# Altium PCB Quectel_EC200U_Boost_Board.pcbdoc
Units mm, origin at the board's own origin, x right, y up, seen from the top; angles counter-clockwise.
Board outline 72.8 x 63.88 mm, 4 copper layers (Top Layer, Inner1, Inner2, Bottom Layer); 116 components, 85 nets, 444 pads, 106 vias.
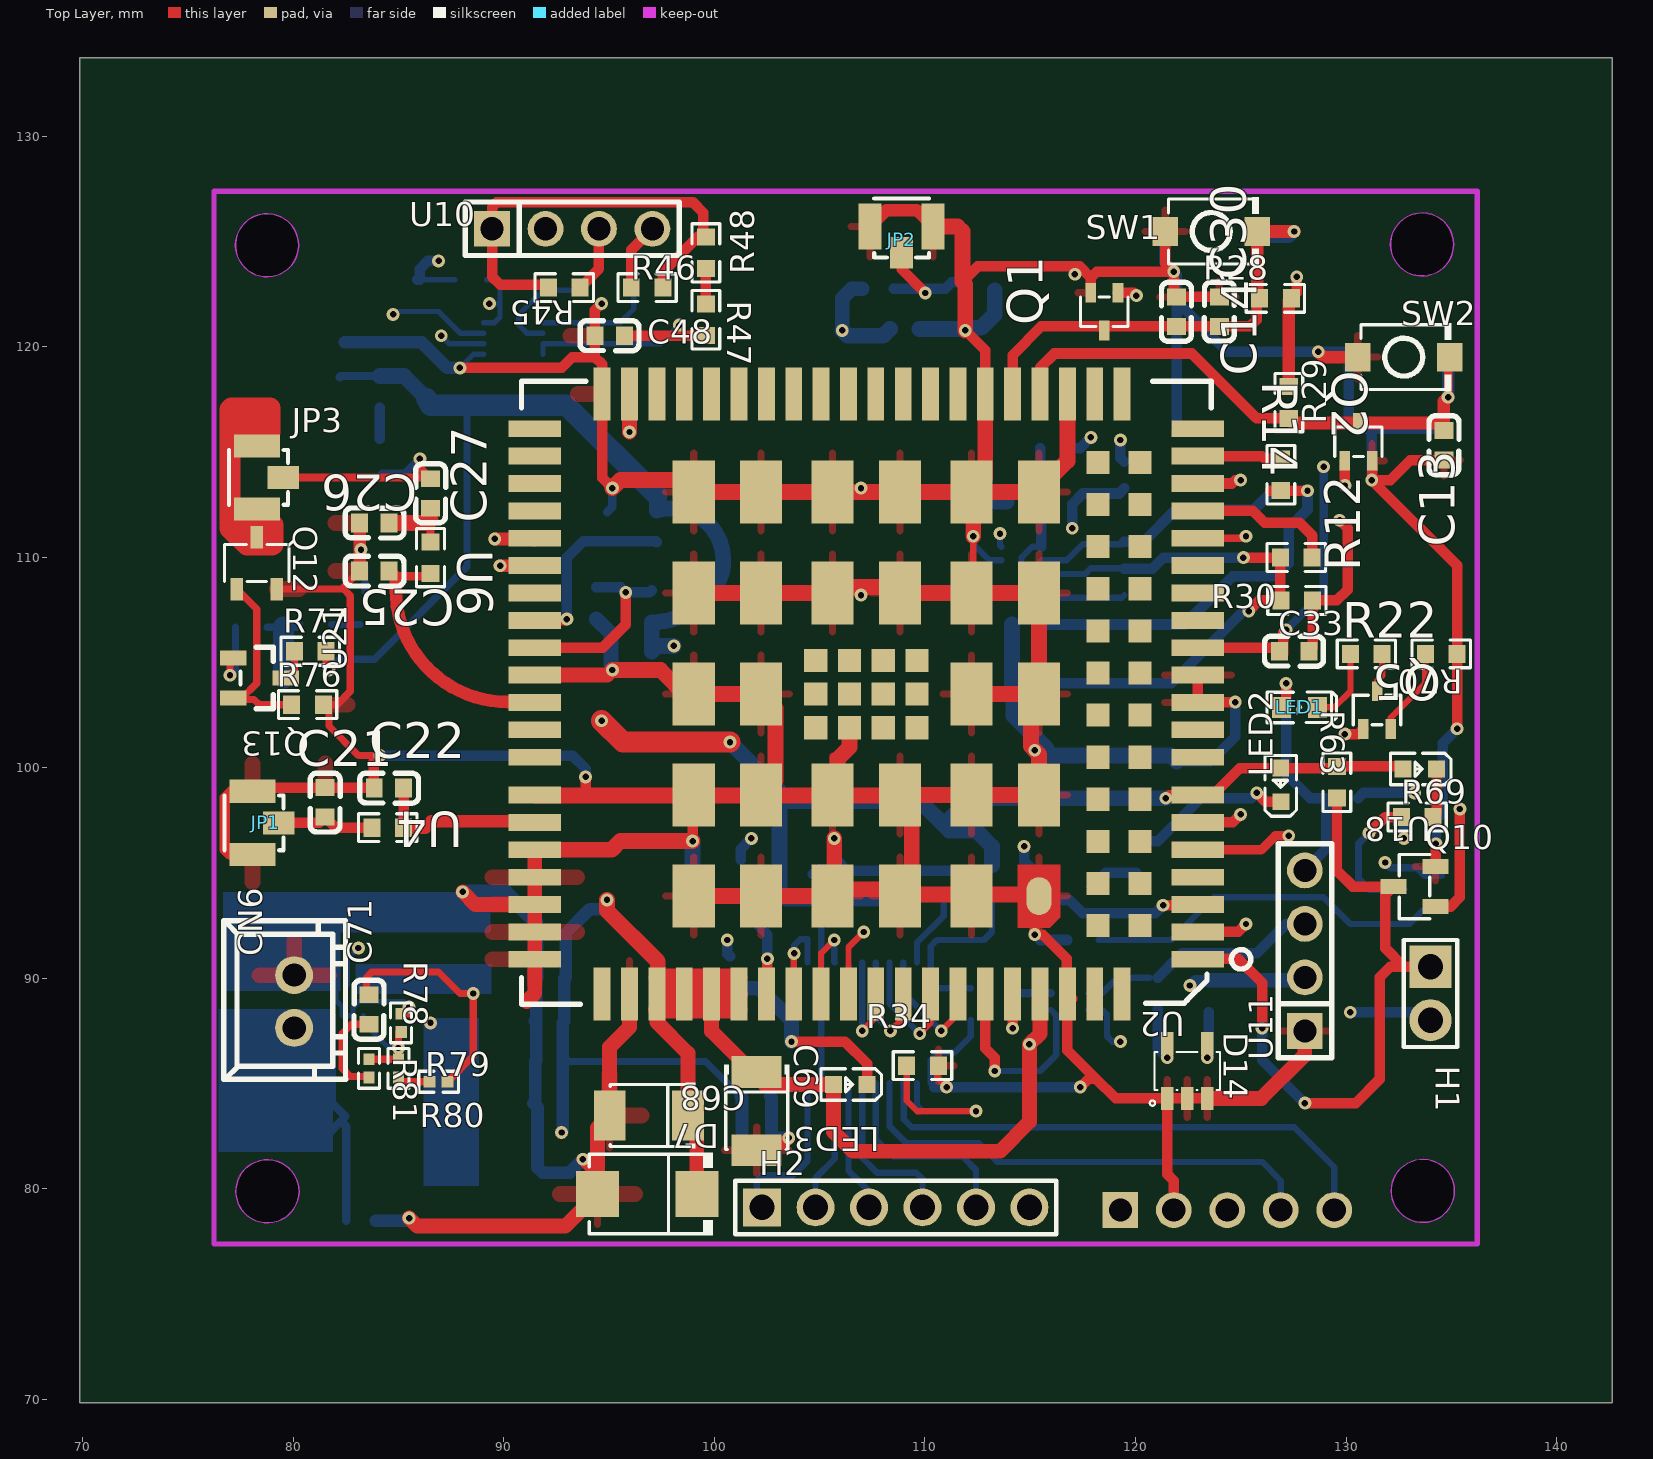
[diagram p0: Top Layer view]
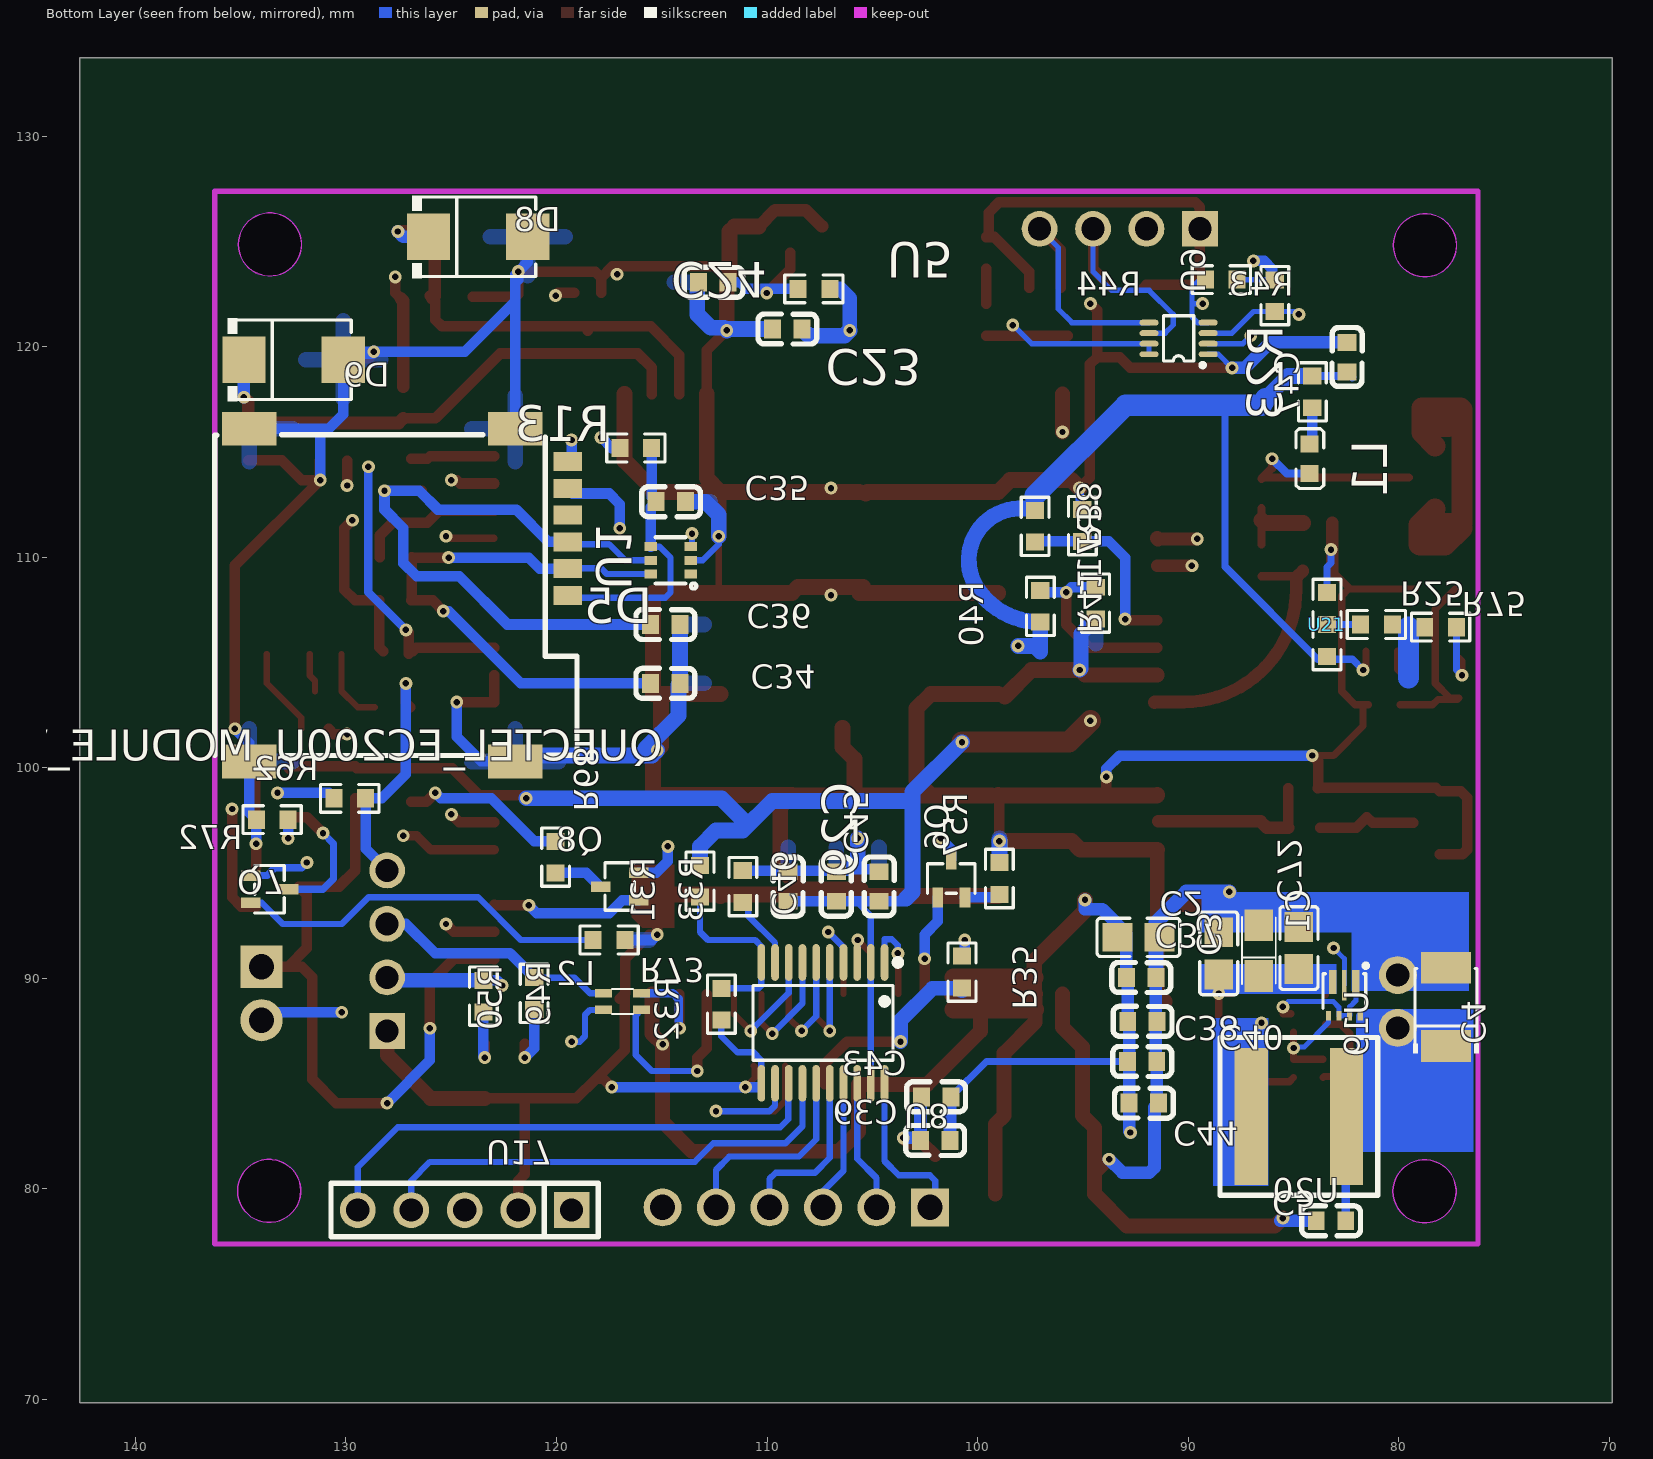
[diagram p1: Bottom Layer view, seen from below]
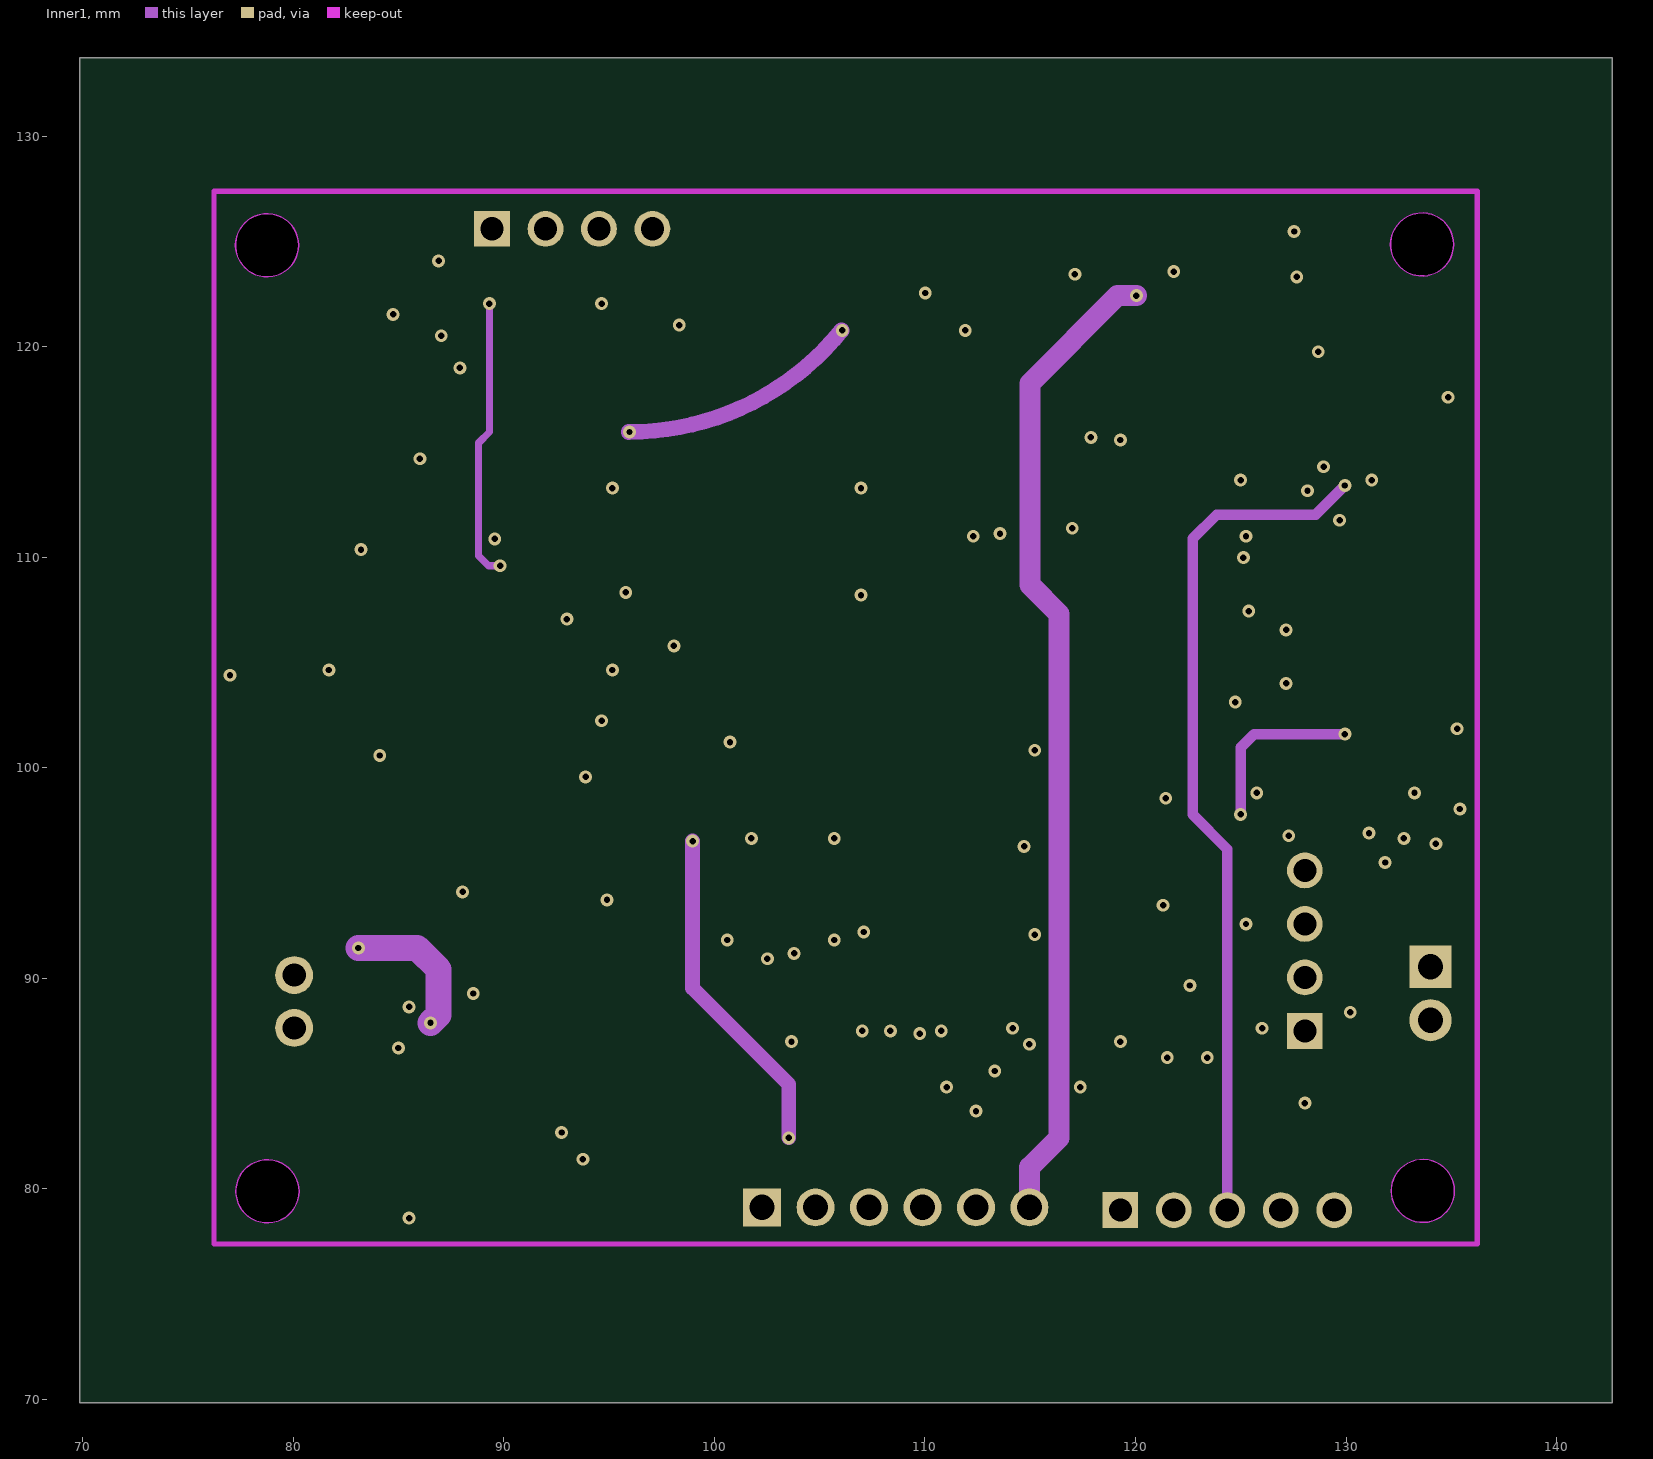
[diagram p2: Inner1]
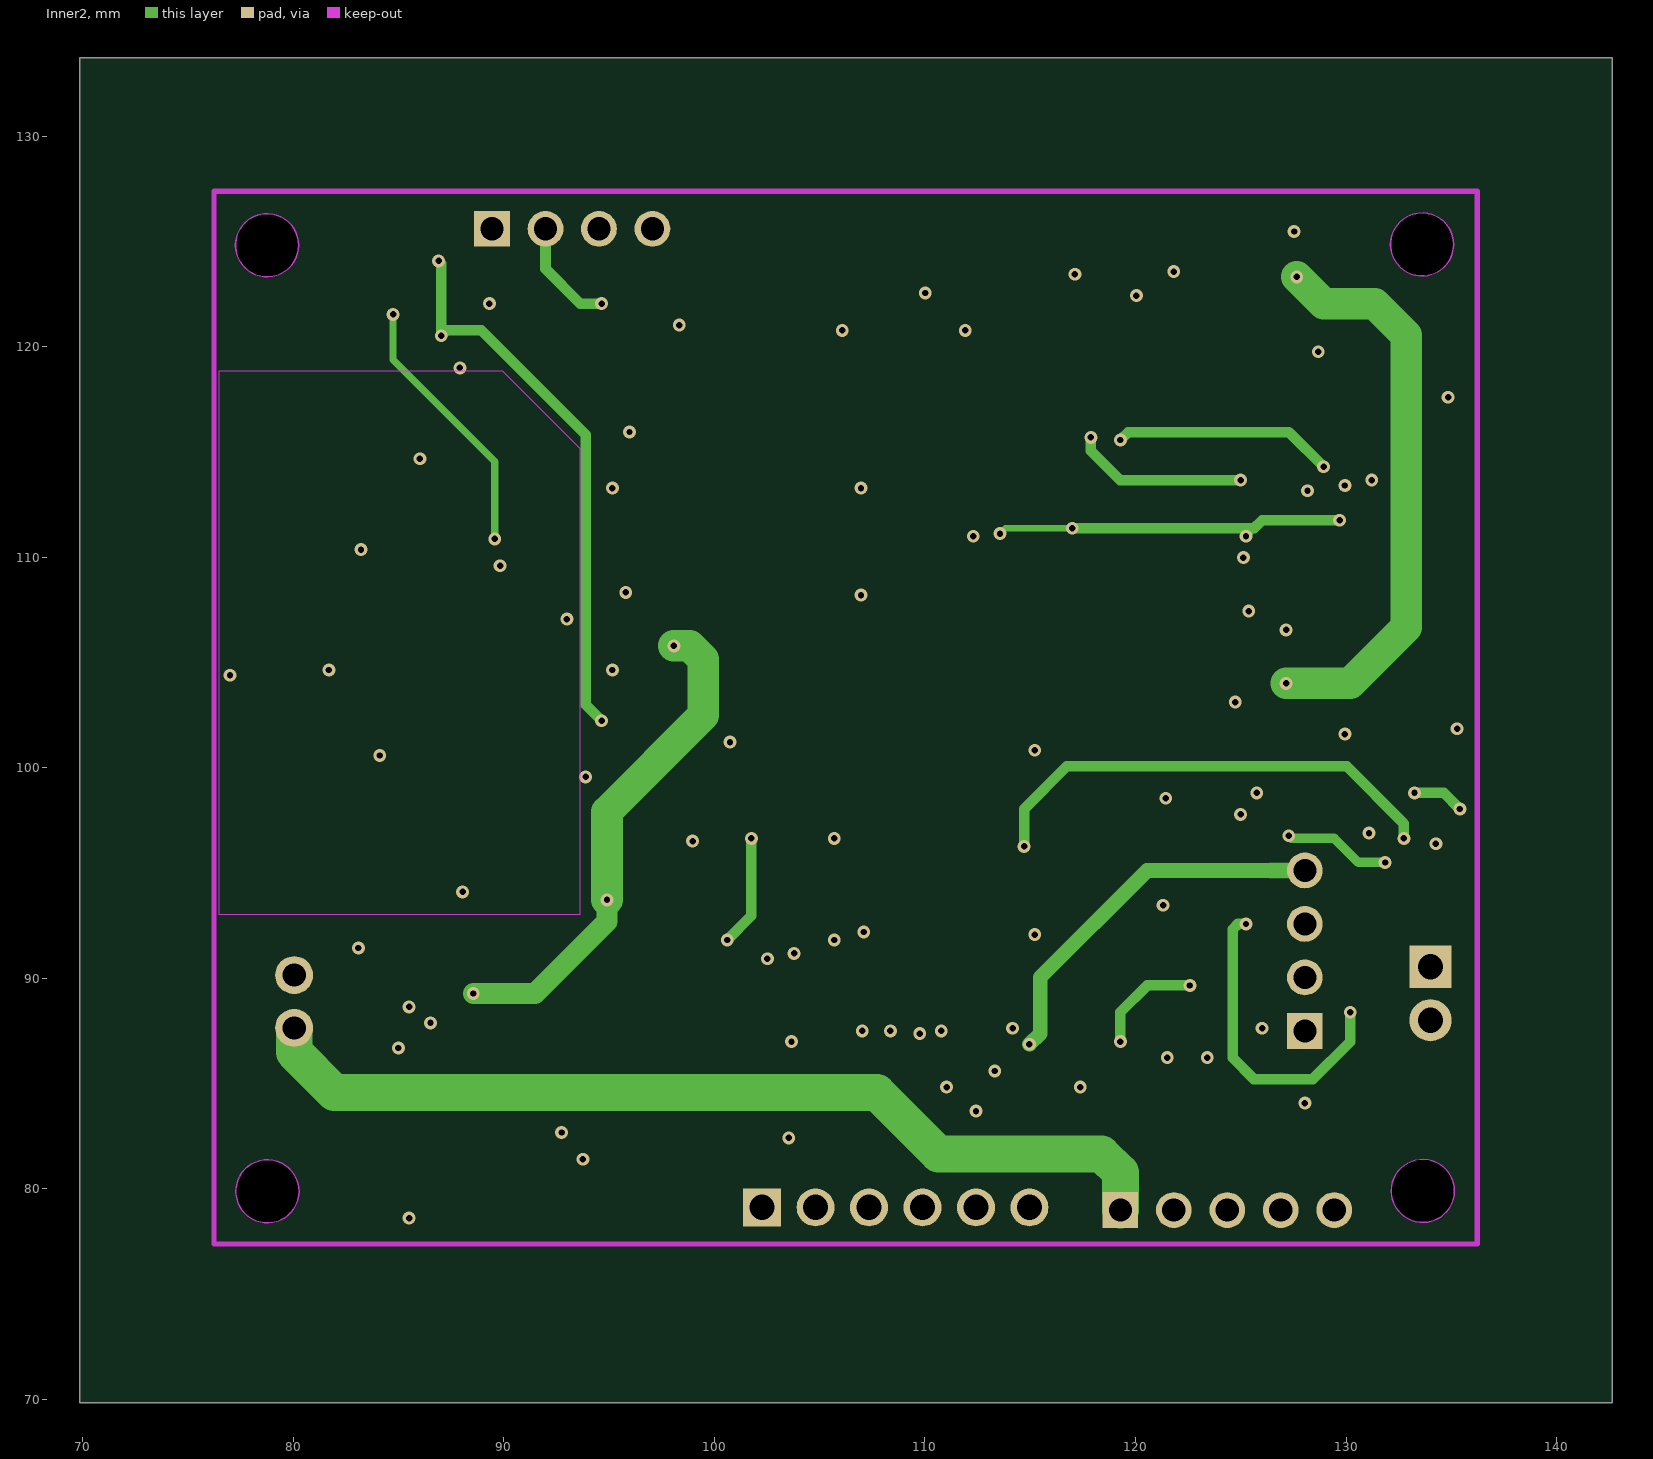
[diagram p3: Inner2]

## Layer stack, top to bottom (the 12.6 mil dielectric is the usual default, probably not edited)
Top Layer: signal copper (thickness not stored)
Dielectric: dielectric 0.32, FR-4, Dk 4.8
Inner1: signal copper (thickness not stored)
Dielectric: dielectric 0.32, FR-4, Dk 4.8
Inner2: signal copper (thickness not stored)
Dielectric: dielectric 0.32, FR-4, Dk 4.8
Bottom Layer: signal copper (thickness not stored)

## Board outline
142.649,69.85 69.85,69.85 69.85,133.731 142.649,133.731
cut-out: 80.268,79.883 cw(c78.768,79.883) 77.268,79.883 cw(c78.768,79.883)
cut-out: 135.15,79.903 cw(c133.65,79.903) 132.15,79.903 cw(c133.65,79.903)
cut-out: 135.112,124.859 cw(c133.612,124.859) 132.112,124.859 cw(c133.612,124.859)
cut-out: 80.25,124.821 cw(c78.75,124.821) 77.25,124.821 cw(c78.75,124.821)

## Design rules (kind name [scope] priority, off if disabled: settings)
BoardOutlineClearance Default [All] p0: genericclearance=0.254 ignorepadtopadclearanceinfootprint=FALSE except(0: Arc-SplitContinuation Track-SplitContinuation SMDPad-SplitContinuation THPad-SplitContinuation Via-SplitContinuation Fill-SplitContinuation Poly-SplitContinuation Region-SplitContinuation Text-SplitContinuation; 0.152: Track-OutlineEdge SMDPad-OutlineEdge THPad-OutlineEdge Via-OutlineEdge Fill-OutlineEdge Region-OutlineEdge Poly-OutlineEdge Text-OutlineEdge Track-CutoutEdge SMDPad-CutoutEdge THPad-CutoutEdge Via-CutoutEdge Fill-CutoutEdge Region-CutoutEdge)
Clearance Default [(InNet('I2C_SCL') OR InNet('VDD_EXT') OR InNet('PWRKEY') OR InNet('RSTKEY') OR InNet('SIM_GND') OR InNet('SIM_VDD') OR InNet('RF_ANT') OR InNet('WIFI/BT_ANT') OR InNet('GNSS_ANT') OR InNet('NW') OR InNet('MAIN_RXD') OR InNet('MAIN_TXD') OR InNet('SIM_CLK') OR InNet('ADC0') OR InNet('ADC1') OR InNet('SIM_DATA') OR InNet('SIM_RST') OR InNet('RKEY') OR InNet('I2C_SDA') OR InNet('PKEY') OR InNet('GND') OR InNet('$1N28') OR InNet('$1N29') OR InNet('$1N30') OR InNet('$1N1314') OR InNet('VBAT') OR InNet('$1N59') OR InNet('$1N67') OR InNet('MCU_TXD') OR InNet('MCU_RXD') OR InNet('MAIN_RI') OR InNet('MAIN_DCD') OR InNet('MAIN_CTS') OR InNet('MAIN_RTS') OR InNet('MAIN_DTR') OR InNet('MCU_RI') OR InNet('MCU_DCD') OR InNet('MCU_CTS') OR InNet('MCU_RTS') OR InNet('MCU_DTR') OR InNet('STATUS') OR InNet('$3N5800') OR InNet('$3N510') OR InNet('$3N512') OR InNet('I2C_SDA2') OR InNet('I2C_SCL2') OR InNet('$3N2253') OR InNet('VCC(3.3V)') OR InNet('$3N3340') OR InNet('$3N3620') OR InNet('$3N3623') OR InNet('USB_DP') OR InNet('USB_DM') OR InNet('$3N3933') OR InNet('$3N3934') OR InNet('NW_MODE') OR InNet('$3N5937') OR InNet('SLEEP_IND') OR InNet('$3N6076') OR InNet('WAKEUP_IN') OR InNet('$3N6217') OR InNet('AP_READY') OR InNet('$3N8732') OR InNet('$3N8771') OR InNet('$3N8850') OR InNet('$3N8845') OR InNet('$1N55959') OR InNet('VCC(2.5V-5V)') OR InNet('$1N55963') OR InNet('$1N55965') OR InNet('$1N55970') OR InNet('$1N42326') OR InNet('$1N42264') OR InNet('$1N42256') OR InNet('$1N42291') OR InNet('$1N42272') OR InNet('$1N42271') OR InNet('GNNS_SIN') OR InNet('GNSS_GND') OR InNet('$1N69113') OR InNet('GNSS_GND_TRG') OR InNet('$1N60604') OR InNet('$1N60546') OR InNet('$1N69275') OR InNet('$1N85973'))] p1: gap=0.178 ignorepadtopadclearanceinfootprint=FALSE except(0: Poly-Poly; 0.152: Track-Track Track-SMDPad SMDPad-SMDPad Track-THPad SMDPad-THPad THPad-THPad Track-Via SMDPad-Via THPad-Via Via-Via Track-Fill SMDPad-Fill THPad-Fill Via-Fill Fill-Fill Track-Region SMDPad-Region THPad-Region Via-Region Fill-Region Region-Region Track-Poly SMDPad-Poly THPad-Poly Via-Poly Fill-Poly Region-Poly Track-Text SMDPad-Text THPad-Text Via-Text Fill-Text Region-Text Poly-Text Text-Text Track-Sheet SMDPad-Sheet THPad-Sheet Via-Sheet Fill-Sheet Region-Sheet Poly-Sheet Text-Sheet Track-Hole SMDPad-Hole THPad-Hole Via-Hole Fill-Hole Region-Hole Poly-Hole Text-Hole Sheet-Hole)
DiffPairsRouting differentialPair [All] p1: maxuncoupledlength=10 minlimit=5.9843 maxlimit=5.9843 mostfreqgap=5.9843 toplayer_minwidth=5 toplayer_prefwidth=10 toplayer_maxwidth=100 bottomlayer_minwidth=5 bottomlayer_prefwidth=10 bottomlayer_maxwidth=100 midlayer1_minwidth=5 midlayer1_prefwidth=10 midlayer1_maxwidth=100 midlayer2_minwidth=5 midlayer2_prefwidth=10 midlayer2_maxwidth=100
PasteMaskExpansion Common [All] p1: expansion=0
PlaneConnect Default [All] p1: planeconnectstyle=Relief reliefexpansion=0.508 reliefentries=4 reliefconductorwidth=0 reliefairgap=0.254
PolygonConnect copperRegion [All] p1: connectstyle=Relief reliefentries=4 reliefconductorwidth=10 polygonreliefangle="90 Angle" airgapwidth=10
PolygonConnect TOP_poly [All] p1: connectstyle=Relief reliefentries=4 reliefconductorwidth=13.3858 polygonreliefangle="90 Angle" airgapwidth=13.3858
PolygonConnect RF_poly [All] p1: connectstyle=Relief reliefentries=4 reliefconductorwidth=29.5276 polygonreliefangle="90 Angle" airgapwidth=29.5276
RoutingVias Default [All] p1: viastyle="Through Hole" holewidth=12.0078 minholewidth=12.0078 maxholewidth=2362.0078 width=24.0158 minwidth=24.0158 maxwidth=3937.9922
SolderMaskExpansion Common [All] p1: useseparateexpansions=TRUE expansion=2.0079 expansionbottom=2.0079
Width Default [All] p1: maxlimit=236 minlimit=8 preferedwidth=10

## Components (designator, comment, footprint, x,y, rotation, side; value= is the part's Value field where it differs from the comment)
C1 "" C0805 84.737,91.44 r270 bottom
C2 "" C0805 92.357,91.948 r0 bottom
C3 "" C0805 88.547,91.186 r270 bottom
C4 "" CASE-B_3528 77.752,88.646 r90 bottom
C5 "" C0603 83.213,78.486 r0 bottom
C13 "10uF" C0603 134.648,115.316 r270 top
C14 "10uF" C0603 121.948,121.666 r90 top
C21 "NM" C0603 81.512,98.358 r90 top
C22 "NM" C0603 84.539,99.039 r180 top
C23 "NM" C0603 109.043,120.845 r0 bottom
C24 "NM" C0603 112.55,123.063 r0 bottom
C25 "NM" C0603 83.848,109.347 r180 top
C26 "NM" C0603 83.848,111.633 r180 top
C27 "100pF" C0603 86.515,113.03 r270 top
C29 "2.2uF" C0603 104.676,94.361 r270 bottom
C30 "10nF" C0603 123.98,121.666 r270 top
C33 "" C0603 127.536,105.537 r0 top
C34 "" C0603 114.836,104.013 r0 bottom
C35 "" C0603 114.567,112.64 r0 bottom
C36 "" C0603 114.836,106.807 r0 bottom
C37 "" C0603 92.23,90.043 r0 bottom
C38 "" C0603 92.186,86.055 r0 bottom
C39 "" C0603 102.009,82.296 r180 bottom
C40 "" C0603 92.17,87.96 r0 bottom
C43 "" C0603 101.962,84.374 r180 bottom
C44 "" C0603 92.103,84.074 r0 bottom
C45 "" C0603 106.708,94.361 r90 bottom
C46 "" C0603 108.994,94.361 r90 bottom
C47 "" C0603 82.451,119.507 r270 bottom
C48 "" C0603 95.024,120.523 r0 top
C68 "" CASE-B_3528 96.882,83.485 r180 top
C69 "" CASE-B_3528 102.009,83.693 r270 top
C71 "" C0603 83.594,88.519 r90 top
C72 "" CASE-A_3216 86.642,91.313 r90 bottom
CN6 "" CONN-TH_XH-2A 80.038,88.9 r90 top
D5 "SMF05C.TCT" SC-70-6_L2.2-W1.3-P0.65-LS2.1-BR 114.582,109.855 r180 bottom
D7 "" SMB_L4.6-W3.6-LS5.3-RD 96.802,79.756 r180 top
D8 "" SMB_L4.6-W3.6-LS5.3-RD 123.726,125.222 r180 bottom
D9 "" SMB_L4.6-W3.6-LS5.3-RD 132.489,119.38 r180 bottom
D14 "" SOT-23-5_L3.0-W1.7-P0.95-LS2.8-BR 122.456,85.598 r270 top
H1 "" HDR-TH_2P-P2.54-V-M 134.013,89.281 r270 top
H2 "" HDR-TH_6P-P2.54-V-M-1 108.613,79.121 r0 top
JP1 "" ANT-SMD_UFL-R-SMT-1-10 78.68,97.384 r180 top
JP2 "U.FL-R-SMT-1(10)" ANT-SMD_UFL-R-SMT-1-10 108.889,125.091 r90 top
JP3 "" ANT-SMD_UFL-R-SMT-1-10 78.895,113.792 r180 top
L1 "47nH" IND-SMD_L1.6-W0.8-1 84.229,114.681 r270 bottom
L2 "" IND-SMD_4P-L2.0-W1.2-TL 116.868,88.9 r180 bottom
LED1 "LED-0603_G" LED0603_GREEN 127.79,102.87 r0 top
LED2 "" LED0603-RD_BLUE 126.901,99.187 r90 top
LED3 "" LED0603-RD 106.454,84.963 r180 top
Q1 "DTC043EUBTL" SOT-323-3_L2.0-W1.3-P1.30-LS2.1-BR 118.519,121.666 r90 top
Q2 "DTC043EUBTL" SOT-323-3_L2.0-W1.3-P1.30-LS2.1-BR 130.588,115.483 r270 top
Q5 "DTC043EUBTL" SOT-323-3_L2.0-W1.3-P1.30-LS2.1-BR 131.473,102.743 r270 top
Q6 "" SOT-323-3_L2.0-W1.3-P1.30-LS2.1-BR 101.247,94.742 r270 bottom
Q7 "" SOT-323-3_L2.0-W1.3-P1.30-LS2.1-BR 133.632,94.234 r0 bottom
Q8 "" SOT-323-3_L2.0-W1.3-P1.30-LS2.1-BR 116.995,94.361 r180 bottom
Q10 "" SOT-23-3_L2.9-W1.3-P1.90-LS2.4-BR 133.251,94.361 r0 top
Q12 "" SOT-23-3_L2.9-W1.6-P1.90-LS2.8-BR 78.26,109.728 r270 top
Q13 "" SOT-23-3_L2.9-W1.3-P1.90-LS2.4-TR 78.387,104.267 r180 top
R12 "0Ω" R0603 127.635,109.991 r180 top
R13 "0Ω" R0603 116.233,115.189 r180 bottom
R14 "0Ω" R0603 126.901,113.919 r270 top
R22 "2.2kΩ" R0603 130.965,105.41 r0 top
R23 "10Ω" R0603 84.102,117.856 r270 bottom
R25 "" R0603 81.054,106.807 r0 bottom
R28 "" R0603 126.647,122.301 r0 top
R29 "" R0603 127.282,117.348 r90 top
R30 "" R0603 127.663,107.95 r0 top
R31 "" R0603 113.185,94.615 r270 bottom
R32 "" R0603 112.169,88.773 r270 bottom
R33 "" R0603 111.153,94.361 r270 bottom
R34 "" R0603 109.883,85.852 r0 top
R35 "2.2kΩ" R0603 100.739,90.297 r90 bottom
R38 "" R0603 97.269,111.469 r90 bottom
R40 "" R0603 97.02,107.669 r270 bottom
R41 "" R0603 94.389,107.823 r90 bottom
R43 "" R0603 85.88,122.428 r90 bottom
R44 "" R0603 88.42,123.19 r180 bottom
R45 "" R0603 92.865,122.809 r180 top
R46 "" R0603 96.802,122.809 r0 top
R47 "" R0603 99.596,121.285 r90 top
R48 "" R0603 99.596,124.46 r90 top
R49 "" R0603 121.059,89.281 r270 bottom
R50 "" R0603 123.472,89.154 r270 bottom
R57 "0Ω" R0603 98.961,94.742 r270 bottom
R62 "" R0603 129.822,98.552 r180 bottom
R63 "" R0603 129.568,99.314 r270 top
R68 "" R0603 120.043,95.758 r90 bottom
R69 "" R0603 133.378,97.663 r0 top
R70 "" R0603 134.521,105.41 r180 top
R71 "" R0603 95.024,111.506 r270 bottom
R72 "" R0603 133.505,97.536 r180 bottom
R73 "" R0603 117.503,91.821 r0 bottom
R75 "" R0603 78.006,106.68 r180 bottom
R76 "" R0603 80.673,102.997 r0 top
R77 "" R0603 80.8,105.537 r180 top
R78 "" R0402 85.118,87.884 r270 top
R79 "" R0402 84.991,85.725 r270 top
R80 "" R0402 86.896,85.09 r0 top
R81 "" R0402 83.594,85.725 r270 top
SW1 "" SW-SMD_L3.9-W3.0-P4.45 123.599,125.476 r0 top
SW2 "" SW-SMD_L3.9-W3.0-P4.45 132.743,119.507 r0 top
U1 "SIM-MICRO-6P" MICRO-SIM-SMD_KH-SIM1616-6PIN 127.028,108.204 r270 bottom
U2 "" LCC-LGA-144_L32.0-W29.0-CAT1-CUIOT-MZ-6 107.216,103.505 r180 top
U4 "CR0603-J/-000ELF" R0603 84.483,97.155 r180 top
U5 "CR0603-J/-000ELF" R0603 107.773,122.75 r0 bottom
U6 "CR0603-J/-000ELF" R0603 86.515,109.982 r90 top
U8 "" TSSOP-20_L6.5-W4.4-P0.65-LS6.4-BL 107.343,87.884 r0 bottom
U9 "" VSSOP-8_L2.3-W2.0-P0.50-LS3.1-BL 90.452,120.396 r90 bottom
U10 "" HDR-TH_4P-P2.54-V-M 93.246,125.603 r0 top
U11 "" HDR-TH_4P-P2.54-V-M 128.044,91.313 r90 top
U17 "" HDR-TH_5P-P2.54-V-M 124.361,78.994 r0 bottom
U18 "" LED0603-RD 133.505,99.949 r180 top
U19 "" VQFN-7_L2.0-W2.0-P0.55-TL_RWU 82.578,89.027 r270 bottom
U20 "" IND-SMD_L7.5-W7.5_XAL7030 84.737,83.439 r180 bottom
U21 "" threepointjumper 83.086,107.061 r270 bottom

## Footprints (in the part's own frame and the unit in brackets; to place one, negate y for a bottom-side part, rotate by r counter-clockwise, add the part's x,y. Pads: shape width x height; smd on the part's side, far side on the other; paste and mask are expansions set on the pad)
ANT-SMD_UFL-R-SMT-1-10 [mm]
  rect 2.2x1.1 smd: 1(0.625,1.5) 3(0.625,-1.5)
  rect 1.5x1.1 smd: 2(-0.625,0.001)
  silkscreen extent -0.85,-1.3 1.95,1.3
C0603 [mm]
  rect 0.8x0.9 smd: 1(-0.7,0) 2(0.7,0)
  silkscreen extent -1.41,-0.71 1.39,0.72
C0805 [mm]
  rect 1.41x1.35 smd: 1(-1,0) 2(1,0)
  silkscreen extent -1.96,-0.9 1.96,0.9
CASE-A_3216 [mm]
  rect 1.5x1.359 smd: 1(-1.2,0) 2(1.2,0)
  silkscreen extent -1.6,-0.8 1.6,0.8
CASE-B_3528 [mm]
  rect 1.506x2.376 smd: 1(-1.861,0) 2(1.861,0)
  silkscreen extent -2.21,-1.55 1.83,1.55
CONN-TH_XH-2A [mm]
  round 1.8 hole 1.1: 1(-1.251,0) 2(1.251,0)
  silkscreen extent -3.69,-2.45 3.83,3.35
HDR-TH_2P-P2.54-V-M [mm]
  rect 2x2 hole 1.2: 1(-1.27,0)
  round 2 hole 1.2: 2(1.27,0)
  silkscreen extent -2.54,-1.27 2.54,1.27
HDR-TH_4P-P2.54-V-M [mm]
  rect 1.7x1.7 hole 1.1: 1(-3.81,0)
  round 1.7 hole 1.1: 2(-1.27,0) 3(1.27,0) 4(3.81,0)
  silkscreen extent -5.08,-1.27 5.08,1.27
HDR-TH_5P-P2.54-V-M [mm]
  rect 1.7x1.7 hole 1.1: 1(-5.08,0)
  round 1.7 hole 1.1: 2(-2.54,0) 3(0,0) 4(2.54,0) 5(5.08,0)
  silkscreen extent -6.35,-1.27 6.35,1.27
HDR-TH_6P-P2.54-V-M-1 [mm]
  rect 1.8x1.8 hole 1.2: 1(-6.35,0)
  round 1.8 hole 1.2: 2(-3.81,0) 3(-1.27,0) 4(1.27,0) 5(3.81,0) 6(6.35,0)
  silkscreen extent -7.62,-1.27 7.62,1.27
IND-SMD_4P-L2.0-W1.2-TL [mm]
  rect 0.8x0.4 smd: 1(-0.901,0.399) 2(-0.899,-0.4) 3(0.9,-0.4) 4(0.901,0.4)
  silkscreen extent -0.5,-0.6 0.5,0.6
IND-SMD_L1.6-W0.8-1 [mm]
  rect 0.8x0.864 smd: 1(0.7,0) 2(-0.7,0)
  silkscreen extent -1.42,-0.65 1.41,0.67
IND-SMD_L7.5-W7.5_XAL7030 [mm]
  rect 1.58x6.5 smd: 1(-2.26,0) 2(2.26,0)
  silkscreen extent -3.75,-3.75 3.75,3.75
LCC-LGA-144_L32.0-W29.0-CAT1-CUIOT-MZ-6 [mm]
  rect 2.5x0.8 smd: 1(-15.75,12.6) 2(-15.75,11.3) 3(-15.75,10) 4(-15.75,8.7) 5(-15.75,7.4) 6(-15.75,6.1) 7(-15.75,4.8) 8(-15.75,0.4) 9(-15.75,-0.9) 10(-15.75,-2.2) 11(-15.75,-3.5) 12(-15.75,-4.8) 13(-15.75,-6.1) 14(-15.75,-7.4) 15(-15.75,-8.7) 16(-15.75,-10) 17(-15.75,-11.3) 18(-15.75,-12.6) 37(15.75,-12.6) 38(15.75,-11.3) 39(15.75,-10) 40(15.75,-8.7) 41(15.75,-7.4) 42(15.75,-6.1) 43(15.75,-4.8) 44(15.75,-3.5) 45(15.75,-2.2) 46(15.75,-0.9) 47(15.75,0.4) 48(15.75,4.8) 49(15.75,6.1) 50(15.75,7.4) 51(15.75,8.7) 52(15.75,10) 53(15.75,11.3) 54(15.75,12.6) 141(-15.75,3) 142(-15.75,1.7) 143(15.75,1.7) 144(15.75,3)
  rect 0.8x2.5 smd: 19(-9.55,-14.25) 20(-8.25,-14.25) 21(-6.95,-14.25) 22(-5.65,-14.25) 23(-4.35,-14.25) 24(-3.05,-14.25) 25(-1.75,-14.25) 26(-0.45,-14.25) 27(0.85,-14.25) 28(2.15,-14.25) 29(3.45,-14.25) 30(4.75,-14.25) 31(6.05,-14.25) 32(7.35,-14.25) 33(8.65,-14.25) 34(9.95,-14.25) 35(11.25,-14.25) 36(12.55,-14.25) 55(12.55,14.25) 56(11.25,14.25) 57(9.95,14.25) 58(8.65,14.25) 59(7.35,14.25) 60(6.05,14.25) 61(4.75,14.25) 62(3.45,14.25) 63(2.15,14.25) 64(0.85,14.25) 65(-0.45,14.25) 66(-1.75,14.25) 67(-3.05,14.25) 68(-4.35,14.25) 69(-5.65,14.25) 70(-6.95,14.25) 71(-8.25,14.25) 72(-9.55,14.25) 113(-10.85,14.25) 114(-12.15,14.25) 115(-10.85,-14.25) 116(-12.15,-14.25)
  rect 1.1x1.1 smd: 73(2.4,1.6) 74(2.4,0) 75(2.4,-1.6) 76(0.8,1.6) 77(0.8,0) 78(0.8,-1.6) 79(-0.8,1.6) 80(-0.8,0) 81(-0.8,-1.6) 82(-2.4,1.6) 83(-2.4,0) 84(-2.4,-1.6) 117(-11,11) 118(-11,9) 119(-11,7) 120(-11,5) 121(-11,3) 122(-11,1) 123(-11,-1) 124(-11,-3) 125(-11,-5) 126(-11,-7) 127(-11,-9) 128(-11,-11) 129(-13,11) 130(-13,9) 131(-13,7) 132(-13,5) 133(-13,3) 134(-13,1) 135(-13,-1) 136(-13,-3) 137(-13,-5) 138(-13,-7) 139(-13,-9) 140(-13,-11)
  rect 2x3 smd: 85(8.2,9.6) 86(8.2,4.8) 87(8.2,0) 88(8.2,-4.8) 89(8.2,-9.6) 90(5,9.6) 91(5,4.8) 92(5,0) 93(5,-4.8) 94(5,-9.6) 95(1.6,9.6) 96(1.6,4.8) 97(1.6,-4.8) 98(1.6,-9.6) 99(-1.6,9.6) 100(-1.6,4.8) 101(-1.6,-4.8) 102(-1.6,-9.6) 103(-5,9.6) 104(-5,4.8) 105(-5,0) 106(-5,-4.8) 107(-5,-9.6) 109(-8.2,4.8) 110(-8.2,0) 111(-8.2,-4.8) 112(-8.2,-9.6)
  oval 1.2x1.8 smd: 108(-8.2,9.6)
  Top Layer region: -9.2,8.1 -7.2,8.1 -7.2,11.1 -8.7,11.1 -9.2,10.6
  silkscreen extent -18.26,-14.86 16.38,14.73
LED0603-RD [mm]
  rect 0.8x0.8 smd: 1(-0.799,0) 2(0.799,0)
  silkscreen extent -1.49,-0.75 1.39,0.76
LED0603-RD_BLUE [mm]
  rect 0.8x0.8 smd: 1(-0.8,-0.004) 2(0.799,0.004)
  silkscreen extent -1.49,-0.75 1.39,0.76
LED0603_GREEN [mm]
  rect 0.9x1 smd: 1(-0.85,0) 2(0.85,0)
  silkscreen extent -1.54,-0.73 1.75,0.73
MICRO-SIM-SMD_KH-SIM1616-6PIN [mm]
  rect 0.9x1.35 smd: 1(-5.07,7.565) 2(-2.53,7.565) 3(0.01,7.565) 4(-6.34,7.565) 5(-3.8,7.565) 6(-1.26,7.565)
  rect 1.6x2.6 smd: 9(-7.9,5.065) 10(7.9,5.065) 11(-7.9,-7.565) 12(7.9,-7.565)
  silkscreen extent -7.62,-9.2 7.62,8
R0402 [mm]
  rect 0.566x0.54 smd: 1(-0.433,0) 2(0.433,0)
  silkscreen extent -0.94,-0.5 0.94,0.5
R0603 [mm]
  rect 0.806x0.864 smd: 1(-0.753,0) 2(0.753,0)
  silkscreen extent -1.39,-0.66 1.39,0.66
SC-70-6_L2.2-W1.3-P0.65-LS2.1-BR [mm]
  rect 0.6x0.42 smd: 1(0.95,-0.65) 2(0.95,0) 3(0.95,0.65) 4(-0.95,0.65) 5(-0.95,0) 6(-0.95,-0.65)
  silkscreen extent -0.7,-1.34 1.22,1.1
SMB_L4.6-W3.6-LS5.3-RD [mm]
  rect 2.047x2.192 smd: 1(-2.361,0) 2(2.361,0)
  silkscreen extent -3.12,-1.96 2.74,1.96
SOT-23-3_L2.9-W1.3-P1.90-LS2.4-BR [mm]
  rect 1.25x0.7 smd: 1(1,-0.95) 2(1,0.95) 3(-1,0)
  silkscreen extent -0.73,-1.53 0.73,1.53
SOT-23-3_L2.9-W1.3-P1.90-LS2.4-TR [mm]
  rect 1.25x0.7 smd: 1(1.25,0.95) 2(1.25,-0.95) 3(-1.25,0)
  silkscreen extent -0.65,-1.46 0.9,1.46
SOT-23-3_L2.9-W1.6-P1.90-LS2.8-BR [mm]
  rect 1.07x0.6 smd: 1(1.235,-0.95) 2(1.235,0.95) 3(-1.235,0)
  silkscreen extent -0.88,-1.54 0.88,1.54
SOT-23-5_L3.0-W1.7-P0.95-LS2.8-BR [mm]
  rect 1.1x0.6 smd: 1(1.3,-0.95) 2(1.3,0) 3(1.3,0.95) 4(-1.3,0.95) 5(-1.3,-0.95)
  silkscreen extent -0.9,-1.78 1.65,1.55
SOT-323-3_L2.0-W1.3-P1.30-LS2.1-BR [mm]
  rect 0.936x0.5 smd: 1(0.898,-0.65) 2(0.898,0.65) 3(-0.898,0)
  silkscreen extent -0.7,-1.13 0.7,1.13
SW-SMD_L3.9-W3.0-P4.45 [mm]
  rect 1.23x1.36 smd: 1(-2.185,0) 2(2.185,0)
  silkscreen extent -2.03,-1.62 2.25,1.62
threepointjumper [mil]
  rect 31.75x34.02 smd: 1(69.66,-12.5) 2(10.34,-12.5) 3(-49.66,-12.5)
  silkscreen extent -75,-39 95,14
TSSOP-20_L6.5-W4.4-P0.65-LS6.4-BL [mm]
  oval 0.364x1.742 smd: 1(-2.925,-2.871) 2(-2.275,-2.871) 3(-1.625,-2.871) 4(-0.975,-2.871) 5(-0.325,-2.871) 6(0.325,-2.871) 7(0.975,-2.871) 8(1.625,-2.871) 9(2.275,-2.871) 10(2.925,-2.871) 11(2.925,2.871) 12(2.275,2.871) 13(1.625,2.871) 14(0.975,2.871) 15(0.325,2.871) 16(-0.325,2.871) 17(-0.975,2.871) 18(-1.625,2.871) 19(-2.275,2.871) 20(-2.925,2.871)
  silkscreen extent -3.71,-3.02 3.33,1.77
VQFN-7_L2.0-W2.0-P0.55-TL_RWU [mm]
  rect 1.15x0.35 smd: 1(-0.8,0.55) 3(-0.8,-0.55)
  rect 1.45x0.2 smd: 2(-0.65,0)
  rect 0.45x0.25 smd: 4(0.8,-0.75) 5(0.8,-0.25) 6(0.8,0.25) 7(0.8,0.75)
  silkscreen extent -1.67,-1.02 0.46,1.12
VSSOP-8_L2.3-W2.0-P0.50-LS3.1-BL [mm]
  oval 0.28x0.905 smd: 1(-0.75,-1.403) 2(-0.25,-1.403) 3(0.25,-1.403) 4(0.75,-1.403) 5(0.75,1.403) 6(0.25,1.403) 7(-0.25,1.403) 8(-0.75,1.403)
  silkscreen extent -1.37,-1.24 1.08,0.72

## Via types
v1: diameter 0.61, hole 0.305, Top Layer to Bottom Layer, 103 vias
v2: diameter 0.61, hole 0.304, Top Layer to Bottom Layer, 3 vias

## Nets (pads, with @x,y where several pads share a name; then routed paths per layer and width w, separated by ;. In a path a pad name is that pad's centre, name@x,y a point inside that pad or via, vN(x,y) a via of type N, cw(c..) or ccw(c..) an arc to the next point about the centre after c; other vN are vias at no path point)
$1N28: C34.2 D5.6 R12.2 R30.1 U1.6 | length 26.7
  Top Layer w0.5: v1(125.123,109.982) R12.2@126.873,109.982 ; v1(125.377,107.442) 125.885,107.95 R30.1 126.873,107.987 R12.2@126.873,109.982 ; R12.2 R12.2@126.873,109.982
  Bottom Layer w0.3: D5.6 117.615,109.205 117.884,109.474 119.454,109.474 U1.6
  Bottom Layer w0.5: C34.2 121.694,104.013 125.123,107.442 v1(125.377,107.442) ; U1.6 120.795,109.464 121.313,109.982 v1(125.123,109.982)
$1N29: C36.2 D5.5 R14.2 U1.2 | length 33
  Top Layer w0.5: R14.2 126.393,113.166 126.402,113.157 v1(128.171,113.157)
  Bottom Layer w0.3: D5.5 116.741,109.855 117.503,110.617 119.346,110.617 U1.2
  Bottom Layer w0.5: C36.2 122.329,106.807 124.615,109.093 126.647,109.093 127.282,109.728 127.282,111.379 128.171,112.268 v1(128.171,113.157) 126.52,113.157 125.631,112.268 121.922,112.268 120.388,110.734 U1.2
$1N30: C35.2 D5.4 R13.2 U1.3 | length 12.7
  Bottom Layer w0.3: D5.4 115.105,110.505 114.582,109.982 114.582,108.331 114.836,108.077 119.346,108.077 U1.3
  Bottom Layer w0.5: R13.2 115.48,112.853 C35.2 115.532,112.375 D5.4
$1N59: C21.1 JP1.2 U4.2 | length 4.7
  Top Layer w0.5: JP1.2 81.237,97.383 C21.1 82.015,97.155 U4.2
$1N67: L1.2 R23.2 | length 1.5
  Bottom Layer w0.5: L1.2@84.102,115.635 R23.2
$1N1314: Q5.3 R22.2 | length 1.9
  Top Layer w0.3: Q5.3 131.473,104.14 131.719,104.385 R22.2
$1N42256: C26.1 C27.2 U6.2 | length 3.7
  Top Layer w0.4: U6.2@86.515,110.608 86.515,111.76 C27.2
  Top Layer w0.75: C26.1 86.388,111.633 86.515,111.76
$1N42264: LED1.2 R22.1 | length 3.7
  Top Layer w0.3: LED1.2 129.441,102.87 130.212,103.641 R22.1
$1N42271: R33.2 U8.9 | length 3.4
  Bottom Layer w0.3: U8.9 109.618,91.683 110.899,92.964 R33.2@110.899,93.608
$1N42272: R34.1 U8.12 | length 9.1
  Top Layer w0.3: R34.1 109.13,84.192 109.629,83.693 v1(112.423,83.693)
  Bottom Layer w0.3: U8.12 109.618,83.958 109.883,83.693 v1(112.423,83.693)
$1N42291: R31.2 R32.1 U8.10 | length 8.7
  Bottom Layer w0.3: R32.1 110.4,89.526 110.268,89.658 U8.10 110.268,91.521 110.568,91.821 112.804,91.821 113.185,92.202 R31.2
$1N42326: Q5.2 R70.2 | length 4.2
  Top Layer w0.3: Q5.2 132.123,102.377 133.768,104.022 R70.2
$1N55959: U20.1 | length 13.5
  Inner1 w1.24: v1(83.086,91.44) 85.88,91.44 86.896,90.424 86.896,88.265 v1(86.515,87.884)
  Bottom Layer w0.245: 82.578,89.677 82.578,90.932 v1(83.086,91.44) ; v1(86.515,87.884) 86.515,83.921 U20.1
$1N55963: R79.2 R80.1 | length 1.6
  Top Layer w0.34: R79.2 85.194,85.09 R80.1
$1N55965: R78.2 R79.1 R81.1 | length 5.2
  Top Layer w0.34: R81.1 R79.1 v1(84.991,86.691) R78.2@84.991,87.451
  Bottom Layer w0.245: 83.328,88.227 83.328,87.896 84.483,86.741 v1@84.991,86.741
$1N55970: C71.1 R81.2 | length 4.4
  Top Layer w0.34: C71.1@83.467,87.819 82.767,87.819 82.324,87.376 82.324,85.725 82.705,85.344 83.543,85.344 R81.2
$1N60546: Q12.1 Q13.1 R76.1 | length 9.2
  Top Layer w0.34: Q12.1 78.26,107.543 78.26,104.013 77.564,103.317 Q13.1 77.204,103.251 78.133,103.251 78.387,102.997 R76.1
$1N60604: Q13.2 R75.2 | length 3.3
  Top Layer w0.34: v1(76.99,104.394) 76.99,105.07 Q13.2
  Bottom Layer w0.34: v1(76.99,104.394) 77.253,104.657 R75.2
$1N69113: C24.1 JP2.2 U5.2 | length 6.1
  Top Layer w0.5: JP2.2 108.888,123.677 v1(110.01,122.555)
  Bottom Layer w0.5: U5.2 v1@109.816,122.75 ; v1(110.01,122.555) v1@109.816,122.75 ; C24.1 111.28,123.063 110.967,122.75 v1@109.816,122.75
$1N69275: Q13.3 R77.2 | length 1.4
  Top Layer w0.34: Q13.3 80.047,104.677 R77.2
$1N85973: R25.2 U21.2 | length 1.3
  Bottom Layer w0.34: R25.2 U21.2@83.152,106.807
$3N510: Q6.3 R35.2 | length 7.3
  Inner2 w0.5: v1(100.612,91.821) 101.755,92.964 v1(101.755,96.647)
  Bottom Layer w0.5: v1(100.612,91.821) 100.612,91.177 R35.2 ; Q6.3 101.247,96.139 v1(101.755,96.647)
$3N512: LED3.1 R35.1 | length 9.6
  Top Layer w0.5: v1(103.66,86.995) 106.2,86.995 107.254,85.942 LED3.1
  Bottom Layer w0.7: R35.1@100.739,89.408 100.866,89.535 102.136,89.535 103.66,88.011 v1(103.66,86.995)
$3N2253: C48.2 R47.1 U9.7 U9.8 | length 13
  Top Layer w0.254: v1(98.326,121.031) 98.326,120.532 R47.1
  Top Layer w0.5: C48.2 99.588,120.523 R47.1
  Bottom Layer w0.254: U9.8 U9.7 97.441,120.146 v1(98.326,121.031)
$3N3340: R47.2 R48.1 | length 1.7
  Top Layer w0.5: R47.2 R48.1
$3N3620: L2.1 R49.1 U11.3 | length 11.2
  Bottom Layer w0.3: L2.1 118.41,89.299 119.146,90.034 R49.1@120.67,90.034
  Bottom Layer w0.5: R49.1 122.211,91.186 125.758,91.186 127.155,92.583 U11.3
$3N3623: L2.2 R50.1 U11.2 | length 13.6
  Inner2 w0.5: v1(119.281,86.995) 119.281,88.392 120.551,89.662 v1(122.583,89.662)
  Bottom Layer w0.3: L2.2 118.411,88.5 118.646,88.265 118.646,87.249 118.9,86.995 v1(119.281,86.995)
  Bottom Layer w0.5: v1(122.583,89.662) 122.829,89.907 R50.1
  Bottom Layer w0.7: R50.1 127.909,89.907 U11.2
$3N3933: D14.5 R49.2 | length 3.1
  Top Layer w0.5: v1(121.506,86.233) D14.5
  Bottom Layer w0.5: R49.2 121.059,86.68 v1(121.506,86.233)
$3N3934: D14.4 R50.2 | length 2.9
  Top Layer w0.5: v1(123.406,86.233) D14.4
  Bottom Layer w0.5: v1(123.406,86.233) 123.472,86.299 R50.2
$3N5800: Q6.2 R57.2 | length 1.5
  Bottom Layer w0.5: R57.2@99.078,93.851 100.591,93.851 Q6.2
$3N5937: R69.2 U18.1 | length 2.4
  Top Layer w0.5: R69.2 134.305,97.836 U18.1
$3N6076: LED2.1 R68.2 | length 8
  Top Layer w0.5: v1(125.758,98.806) 126.177,98.387 LED2.1
  Bottom Layer w0.5: R68.2 121.051,96.511 123.091,98.552 125.504,98.552 v1(125.758,98.806)
$3N6217: Q10.1 R62.1 | length 10.8
  Top Layer w0.5: Q10.1 134.968,93.411 135.41,93.853 v1(135.41,98.044)
  Inner2 w0.5: v1(133.251,98.806) 134.648,98.806 v1(135.41,98.044)
  Bottom Layer w0.5: R62.1 130.83,98.806 v1(133.251,98.806)
$3N8732: Q8.3 R68.1 | length 2.4
  Bottom Layer w0.5: Q8.3 117.947,94.361 118.591,95.005 R68.1
$3N8771: Q7.3 R69.1 | length 6.6
  Top Layer w0.5: v1(131.092,96.901) 131.854,97.663 R69.1
  Bottom Layer w0.35: v1(131.092,96.901) 130.592,96.401 130.592,94.734 131.092,94.234 Q7.3
$3N8845: Q7.2 R73.2 | length 18.1
  Bottom Layer w0.3: R73.2 121.694,91.821 123.726,93.853 128.933,93.853 130.203,92.583 132.997,92.583 133.998,93.584 Q7.2
$3N8850: Q8.2 R72.2 | length 25.7
  Inner2 w0.5: v1(114.709,96.266) 114.709,98.044 116.741,100.076 130.03,100.076 132.752,97.354 v1(132.752,96.647)
  Bottom Layer w0.5: v1(114.709,96.266) 114.709,95.559 115.257,95.011 Q8.2 ; v1(132.752,96.647) R72.2
ADC0: R40.1 R41.2 U2.45 | length 9.1
  Top Layer w0.5: U2.45 94.684,105.705 95.786,106.807 v1(95.786,108.331)
  Bottom Layer w0.5: R41.2 95.541,108.576 v1(95.786,108.331) 96.928,108.331 R40.1
ADC1: R38.1 R71.2 U2.44 | length 9.1
  Top Layer w0.5: U2.44 92.936,107.005 v1(92.992,107.061)
  Bottom Layer w0.5: v1(92.992,107.061) 92.992,109.982 93.763,110.753 R71.2 97.232,110.753 R38.1
AP_READY: H1.2 U2.2 | length 21.4
  Top Layer w0.5: U2.2 124.872,92.205 v1(125.25,92.583)
  Inner2 w0.5: v1(125.25,92.583) 124.869,92.583 124.615,92.329 124.615,86.225 125.623,85.217 128.425,85.217 130.203,86.995 v1(130.203,88.392)
  Bottom Layer w0.5: v1(130.203,88.392) 133.632,88.392 H1.2
GND: C1.1 C2.1 C3.1 C4.2 C5.2 C13.2 C14.2 C21.2 C22.2 C23.2 C24.2 C25.2 C26.2 C29.1 C30.1 C34.1 C35.1 C36.1 C37.1 C38.1 C39.1 C40.1 C43.1 C44.1 C45.2 C46.2 C47.1 C48.1 C68.2 C69.2 C72.2 CN6.2 D5.2 D7.2 D8.2 D9.2 D14.1 D14.2 D14.3 JP1.1 JP1.3 JP2.1 JP2.3 Q1.2 Q2.2 Q10.2 Q12.2 R32.2 R33.1 R34.2 R41.1 R57.1 R70.1 R71.1 R72.1 R73.1 R76.2 R78.1 SW1.1 SW2.1 U1.9 U1.10 U1.11 U1.12 U2.8 U2.9 U2.19 U2.22 U2.36 U2.46 U2.48 U2.50 U2.51 U2.52 U2.53 U2.54 U2.56 U2.72 U2.76 U2.85 U2.86 U2.87 U2.88 U2.89 U2.90 U2.91 U2.92 U2.93 U2.94 U2.95 U2.96 U2.97 U2.98 U2.99 U2.100 U2.101 U2.102 U2.103 U2.104 U2.105 U2.106 U2.107 U2.108 U2.109 U2.110 U2.111 U2.112 U8.11 U9.1 U10.2 U11.1 U17.2 U19.1 U21.3 | length 469
  Top Layer w0.3: R34.2 110.581,85.796 110.581,85.282 v1(111.026,84.836) ; v1(112.296,110.998) 112.296,108.471 U2.106@112.462,108.305
  Top Layer w0.34: Q12.2 82.294,108.493 ; R76.2 R76.2@81.689,102.997 ; C25.2 82.294,108.493 ; v1(84.102,100.584) 83.086,100.584 81.689,101.981 R76.2@81.689,102.997 ; R78.1 85.499,88.317 v1(85.499,88.646) ; R76.2@81.689,102.997 82.07,102.997 82.705,103.632 82.705,108.173 82.386,108.493 82.294,108.493
  Top Layer w0.5: JP1.1 76.97,95.885 76.736,96.118 76.736,98.573 77.048,98.885 JP1.3 78.229,99.058 C21.2 C22.2@83.82,99.058 ; C22.2 C22.2@83.82,99.058 ; v1(84.102,100.584) 83.82,100.301 C22.2@83.82,99.058 ; v1(87.912,118.999) 92.738,118.999 93.246,119.507 94.324,119.507 ; 93.732,98.679 93.881,98.828 v1(93.881,99.568) ; v1(94.643,122.047) 94.324,121.728 C48.1 94.324,119.507 ; v1(95.151,113.284) 94.666,113.769 U2.36 94.666,119.165 94.324,119.507 ; v1(98.961,96.52) 98.961,98.65 U2.86@98.99,98.679 ; 111.788,123.095 112.518,123.825 117.345,123.825 117.884,123.286 ; v1(111.915,120.777) 112.866,119.826 U2.22 ; U2.108 115.217,93.706 v1(115.217,92.075) 115.598,92.075 116.741,90.932 116.741,89.281 U2.72@116.995,89.027 ; U2.72 116.766,86.589 118.122,85.233 ; v1(117.376,84.836) 117.773,85.233 118.122,85.233 ; Q1.2 117.884,122.579 117.884,123.286 ; SW1.1 121.414,123.978 v1(121.821,123.571) ; U17.2 121.821,80.391 121.506,80.706 D14.1 ; U2.9 U2.8 122.985,103.124 v1(124.742,103.124) ; D14.3@123.326,84.298 D14.2 D14.1 ; C30.1 C14.2 121.821,122.493 v1(121.821,123.571) ; Q2.2 131.238,113.684 v1(131.219,113.665) ; Q10.2 134.267,95.327 v1(134.267,96.393) ; C13.2 133.059,114.616 132.108,113.665 v1(131.219,113.665) ; v1(135.275,101.854) R70.1 135.275,109.61 v1(131.219,113.665) ; 117.884,123.286 118.169,123.571 v1(121.821,123.571) ; 118.122,85.233 119.057,84.298 D14.1
  Top Layer w0.6: C25.2 C26.2 ; v1(93.754,81.407) D7.2@94.442,80.72 ; C69.2@102.009,81.578 102.609,82.178 103.289,82.178 v1(103.533,82.423) ; JP2.1 108.166,126.492 109.613,126.492 JP2.3 ; v1(128.679,119.761) 128.933,119.507 SW2.1
  Top Layer w0.7: v1(85.499,78.613) 85.88,78.232 92.918,78.232 D7.2 94.442,80.72 94.442,82.906 C68.2 95.021,86.738 95.966,87.683 U2.56 ; v1(88.039,94.107) 88.641,93.505 U2.52 ; 91.087,88.9 91.468,89.281 91.468,90.903 U2.54 U2.53 U2.52 ; U2.50 U2.51 U2.52 ; U2.46 94.908,104.405 v1(95.151,104.648) ; D14.3 125.982,84.298 128.044,86.36 U11.1
  Top Layer w0.75: U2.50 95.117,96.105 95.532,96.52 v1(98.961,96.52) ; U2.48 91.492,98.679 93.732,98.679 98.99,98.679 U2.86 ; v1(95.151,104.648) 97.437,104.648 U2.87@98.707,103.378 ; v1(95.151,113.284) 95.532,113.665 98.456,113.665 U2.89 U2.94 105.236,113.105 U2.98@105.311,113.03 ; U2.85 U2.90 U2.95@105.311,93.905 ; U2.87 U2.92 102.898,102.823 102.898,99.387 U2.91 U2.91@102.19,98.679 ; U2.88 U2.93 U2.97 ; U2.86@99.342,98.679 U2.91@102.19,98.679 ; U2.97@105.438,108.585 108.536,108.585 U2.101 U2.106 112.462,108.305 U2.111 U2.110 U2.110@115.035,103.505 ; U2.95 U2.95@105.311,93.905 ; U2.96 U2.96@105.591,98.679 ; U2.98 U2.102 U2.107 ; v1(105.692,96.647) 105.692,94.361 U2.95@105.565,94.234 ; U2.76 106.416,100.98 105.848,100.412 U2.96@105.848,98.679 ; U2.99@108.613,94.488 109.375,95.25 109.375,98.146 U2.100 ; U2.99 108.487,94.234 U2.95@105.565,94.234 ; U2.99@109.121,93.98 U2.103@112.141,93.98 ; JP2.3 111.549,125.716 111.788,125.476 111.788,123.095 111.915,122.968 v1(111.915,120.777) ; U2.103 U2.103@112.141,93.98 ; U2.105 U2.110@115.035,103.505 ; v1(112.296,110.998) 112.296,113.025 U2.107 ; U2.22 112.866,113.755 U2.107 ; U2.108 115.341,93.98 U2.103@112.141,93.98 ; U2.112 U2.107 ; U2.112@115.598,113.411 116.766,114.579 U2.19 ; U2.91@102.19,98.679 U2.96@105.591,98.679 ; U2.95@105.311,93.905 105.565,94.159 U2.95@105.565,94.234 ; U2.96@105.591,98.679 U2.96@105.848,98.679 ; U2.96@105.848,98.679 108.79,98.679 U2.100 ; U2.100 U2.104 U2.109 115.416,100.639 v1(115.217,100.838) 115.035,101.021 U2.110@115.035,103.505
  Inner1 w0.7: v1(98.961,96.52) 98.961,89.535 103.533,84.963 v1(103.533,82.423)
  Inner2 w0.5: U10.2 91.976,123.698 93.627,122.047 v1(94.643,122.047)
  Bottom Layer w0.245: 82.328,88.227 82.828,88.227
  Bottom Layer w0.25: U19.1 82.029,88.942 82.324,88.646 82.324,88.231 82.328,88.227 ; 82.828,88.227 82.828,88.622 83.106,88.9 85.245,88.9 v1(85.499,88.646)
  Bottom Layer w0.254: v1(87.912,118.999) 88.559,119.646 U9.1
  Bottom Layer w0.3: U8.11@110.445,84.836 U8.11 110.268,86.11 110.645,86.487 111.407,86.487 112.169,87.249 R32.2 ; v1(112.296,110.998) 112.296,110.617 113.058,109.855 D5.2
  Bottom Layer w0.34: v1(83.213,110.363) 83.213,109.728 83.404,109.537 U21.3
  Bottom Layer w0.4: R71.1@94.906,112.141 R71.1 95.151,112.386 v1(95.151,113.284)
  Bottom Layer w0.5: v1(84.102,100.584) 93.246,100.584 93.881,99.949 v1(93.881,99.568) ; C29.1@104.676,94.934 104.93,95.188 105.819,95.188 105.946,95.315 106.147,95.114 R33.1 ; U8.11@110.445,84.836 v1(111.026,84.836) v1(117.376,84.836) ; v1(115.217,92.075) 115.471,91.821 R73.1 ; D8.2 121.366,124.027 v1(121.821,123.571) ; U1.10 123.573,100.304 124.742,101.473 v1(124.742,103.124) ; U1.9 121.963,122.159 ; v1(128.679,119.761) 124.361,119.761 121.963,122.159 ; D9.2 130.129,116.788 130.812,116.104 131.056,116.104 ; v1(131.219,113.665) 131.219,115.941 131.056,116.104 ; v1(134.267,96.393) 134.259,96.402 R72.1 134.593,97.871 U1.12 134.593,101.173 v1(135.275,101.854) ; U1.11 131.056,116.104 ; v1(121.821,123.571) 121.963,123.429 121.963,123.048 ; v1(121.821,123.571) 121.821,123.19 121.963,123.048 ; 121.963,122.159 121.963,123.048
  Bottom Layer w0.6: C47.1 86.099,120.207 87.307,118.999 v1(87.912,118.999) ; C5.2 85.626,78.486 v1(85.499,78.613) ; C40.1 C40.1@91.53,88.02 ; C37.1 C40.1@91.53,88.02 ; v1(93.754,81.407) 93.119,80.772 91.838,80.772 91.595,81.014 91.595,83.882 C44.1 91.486,84.156 C38.1 91.53,86.1 C40.1@91.53,88.02 ; C43.1 102.709,84.326 C39.1 102.836,82.423 v1(103.533,82.423) ; v1(128.679,119.761) 128.732,119.709 130.457,119.709 D9.2
  Bottom Layer w0.7: v1(88.039,94.107) 90.071,94.107 91.53,92.648 C37.1 ; R41.1 95.089,106.37 95.089,104.71 v1(95.151,104.648)
  Bottom Layer w0.75: R57.1 v1(98.961,96.52) ; v1(105.692,96.647) 105.692,95.569 105.946,95.315 ; C23.2 111.848,120.845 v1(111.915,120.777) 112.042,120.904 112.677,120.904 113.312,121.539 C24.2@113.312,122.682 ; v1(112.296,110.998) 112.296,112.014 112.922,112.64 C35.1 ; C36.1 C34.1 114.201,103.948 114.201,102.489 115.789,100.902 115.471,100.584 ; v1(115.217,100.838) 115.471,100.584 ; U1.10 121.683,100.584 115.471,100.584
  other v2: 106.962,108.204 106.962,113.284 117.122,123.444
GNNS_SIN: C27.1 JP3.2 L1.1 | length 10.2
  Top Layer w0.4: JP3.2 C27.1@86.455,113.791 ; v1(86.007,114.681) 86.007,114.238 C27.1@86.455,113.791 ; C27.1 C27.1@86.455,113.791
  Bottom Layer w0.4: L1.1 85.307,113.981 v1(86.007,114.681)
GNSS_ANT: C25.1 U2.47 U6.1 | length 12.5
  Top Layer w0.4: C25.1@84.794,109.102 U6.1@86.515,109.102
  Top Layer w0.6: C25.1 84.794,109.102 84.864,109.031 84.864,108.458 ccw(c90.198,108.458) 90.198,103.124 91.574,103.124 cw(c91.574,103.105) U2.47@91.593,103.105
GNSS_GND: JP3.1 JP3.3 Q12.3 | length 16.9
  Top Layer w1: 76.99,111.379 77.787,110.582 Q12.3@78.387,110.582 ; Q12.3@78.27,111.158 77.821,111.607 76.99,111.607 76.99,116.84 ; JP3.1 79.022,111.54 79.022,110.617 78.987,110.582 Q12.3@78.514,110.582 ; JP3.3 78.895,115.917 78.895,117.094 77.058,117.094 76.99,117.026 76.99,116.84 ; 78.514,116.205 77.625,116.205 76.99,116.84
GNSS_GND_TRG: R25.1 R75.1 | length 4
  Bottom Layer w0.34: R75.1 79.539,106.68 80.174,106.68 R25.1
  Bottom Layer w1: 79.53,104.267 79.539,104.276 79.539,106.68
I2C_SCL: R43.1 U2.41 U9.3 | length 19.4
  Top Layer w0.6: v1(89.563,110.871) U2.41@91.432,110.871
  Top Layer w0.7: U2.41@91.432,110.871 U2.41
  Inner2 w0.34: v1(84.737,121.539) 84.737,119.38 89.563,114.554 v1(89.563,110.871)
  Bottom Layer w0.254: v1(84.737,121.539) 84.873,121.675 R43.1 86.888,121.675 87.916,120.646 U9.3
I2C_SCL2: R45.1 U9.6 U10.3 | length 11.7
  Top Layer w0.5: R45.1 94.516,123.707 U10.3
  Bottom Layer w0.254: U9.6 91.091,120.646 90.706,121.031 90.706,121.539 91.849,122.682 93.627,122.682 94.516,123.571 U10.3
I2C_SDA: R44.1 U2.42 U9.4 | length 18.6
  Top Layer w0.6: v1(89.817,109.601) 89.821,109.605 U2.42
  Inner1 w0.34: v1(89.309,122.047) 89.309,115.951 88.801,115.443 88.801,110.068 89.268,109.601 v1(89.817,109.601)
  Bottom Layer w0.254: U9.4 89.551,121.146 89.817,121.412 89.817,122.047 ; R44.1 89.436,123.19 89.817,122.809 89.817,122.047 ; v1(89.309,122.047) 89.817,122.047
I2C_SDA2: R46.1 U9.5 U10.4 | length 12
  Top Layer w0.5: R46.1 96.049,124.596 U10.4
  Bottom Layer w0.254: U9.5 95.52,121.146 96.167,121.793 96.167,124.714 U10.4
MAIN_CTS: U2.64 U8.4 | length 5
  Top Layer w0.3: U2.64@106.368,89.257 106.368,91.481 v1(107.089,92.202)
  Bottom Layer w0.3: U8.4 106.368,91.481 v1(107.089,92.202)
MAIN_DCD: U2.63 U8.3 | length 3.9
  Top Layer w0.3: U2.63 105.066,91.195 v1(105.692,91.821)
  Bottom Layer w0.3: v1(105.692,91.821) 105.692,90.781 U8.3
MAIN_DTR: U2.66 U8.6 | length 5.5
  Top Layer w0.3: v1(108.359,87.503) 108.966,88.11 U2.66
  Bottom Layer w0.3: U8.6 107.668,88.194 v1(108.359,87.503)
MAIN_RI: U2.62 U8.1 | length 4.2
  Top Layer w0.3: U2.62 103.766,91.165 v1(103.787,91.186)
  Bottom Layer w0.3: v1(103.787,91.186) 103.787,91.567 104.081,91.86 104.418,91.86 U8.1
MAIN_RTS: U2.65 U8.5 | length 5.3
  Top Layer w0.3: v1(107.019,87.503) 107.666,88.151 U2.65
  Bottom Layer w0.3: v1(107.019,87.503) U8.5
MAIN_RXD: U2.68 U8.8 | length 6.1
  Top Layer w0.3: v1(110.772,87.503) 111.566,88.297 U2.68
  Bottom Layer w0.3: U8.8 108.968,89.307 v1(110.772,87.503)
MAIN_TXD: U2.67 U8.7 | length 6.1
  Top Layer w0.3: v1(109.756,87.376) 110.266,87.886 U2.67
  Bottom Layer w0.3: U8.7 108.318,88.814 v1(109.756,87.376)
MCU_CTS: H2.3 U8.17 | length 6.3
  Bottom Layer w0.3: U8.17 106.368,80.858 107.343,79.883 H2.3
MCU_DCD: H2.2 U8.18 | length 6.3
  Bottom Layer w0.3: H2.2 104.803,80.518 105.718,81.433 U8.18
MCU_DTR: H2.5 U8.15 | length 9.8
  Bottom Layer w0.3: U8.15 107.668,82.352 108.486,81.534 111.788,81.534 112.423,80.899 H2.5
MCU_RI: H2.1 U8.20 | length 7.9
  Bottom Layer w0.3: H2.1 102.009,79.375 102.009,80.391 102.263,80.645 103.737,80.645 104.418,81.326 U8.20
MCU_RTS: H2.4 U8.16 | length 8.2
  Bottom Layer w0.3: U8.16 107.019,81.478 107.724,80.772 109.583,80.772 109.883,80.472 H2.4
MCU_RXD: U8.13 U17.5 | length 25.1
  Bottom Layer w0.3: U8.13 108.994,84.987 108.994,83.312 109.375,82.931 127.536,82.931 129.441,81.026 U17.5
MCU_TXD: U8.14 U17.4 | length 23.1
  Bottom Layer w0.3: U8.14 108.318,82.972 109.121,82.169 112.55,82.169 113.439,81.28 126.012,81.28 126.901,80.391 U17.4
NW: Q5.1 U2.6 | length 11.6
  Top Layer w0.5: U2.6 124.619,97.405 124.996,97.782 v1(124.996,97.79) ; v1(129.949,101.6) 130.578,101.6 Q5.1
  Inner1 w0.5: v1(124.996,97.79) 124.996,100.965 125.631,101.6 v1(129.949,101.6)
NW_MODE: Q7.1 U2.5 | length 12.6
  Top Layer w0.45: U2.5 125.978,96.105 126.647,96.774 v1(127.282,96.774)
  Inner2 w0.45: v1(127.282,96.774) 127.409,96.647 129.441,96.647 130.584,95.504 v1(131.854,95.504)
  Bottom Layer w0.35: v1(131.854,95.504) 132.108,95.25 133.378,95.25 133.744,94.884 Q7.1
PKEY: H2.6 Q1.1 | length 48
  Top Layer w0.5: Q1.1 119.907,122.564 v1(120.043,122.428)
  Inner1 w1: H2.6 114.963,81.026 116.363,82.426 116.363,107.312 114.979,108.696 114.979,118.253 119.154,122.428 v1(120.043,122.428)
PWRKEY: C14.1 C30.2 D8.1 Q1.3 R28.1 SW1.2 U2.21 | length 22.1
  Top Layer w0.5: U2.21 114.166,119.599 115.533,120.966 Q1.3@118.519,120.966 ; Q1.3 Q1.3@118.519,120.966 ; R28.1@126.012,122.419 R28.1 125.758,122.165 125.758,121.285 125.439,120.966 C30.2 C14.1 Q1.3@118.519,120.966
  Top Layer w0.6: R28.1 125.784,122.411 SW1.2 v1(127.536,125.476)
  Bottom Layer w0.6: D8.1 127.282,125.222 v1(127.536,125.476)
RF_ANT: C22.1 U2.49 U4.1 | length 8.3
  Top Layer w0.3: U2.49@91.416,97.455 U2.49
  Top Layer w0.5: U4.1 85.239,97.157 C22.1
  Top Layer w0.6: U4.1 86.261,97.155 86.561,97.455 U2.49@91.416,97.455
RKEY: Q2.1 U17.3 | length 42
  Top Layer w0.5: Q2.1 129.949,114.574 v1(129.949,113.411)
  Inner1 w0.5: U17.3 124.361,96.139 122.71,97.79 122.71,110.871 123.853,112.014 128.552,112.014 v1(129.949,113.411)
RSTKEY: C13.1 D9.1 Q2.3 R29.1 SW2.2 U2.20 | length 27.6
  Top Layer w0.4: v1(134.85,117.602) 134.85,119.429 SW2.2
  Top Layer w0.5: U2.20 115.466,118.994 116.152,119.68 122.664,119.68 125.75,116.595 R29.1
  Top Layer w0.6: R29.1 127.496,116.381 Q2.3 134.284,116.381 C13.1 134.648,117.4 v1(134.85,117.602)
  Bottom Layer w0.6: v1(134.85,117.602) D9.1
SIM_CLK: R13.1 U2.16 | length 11.5
  Top Layer w0.5: U2.16 124.582,113.505 124.742,113.665 v1(124.996,113.665)
  Inner2 w0.5: v1(117.884,115.697) 117.884,115.062 119.281,113.665 v1(124.996,113.665)
  Bottom Layer w0.5: R13.1 117.376,115.189 v1(117.884,115.697)
SIM_DATA: R12.1 U2.15 | length 7
  Top Layer w0.5: U2.15 125.567,112.205 126.139,111.633 127.79,111.633 128.389,111.035 R12.1
SIM_GND: C33.1 U1.4 U2.10 | length 25.2
  Top Layer w0.5: U2.10 126.668,105.705 C33.1 ; C33.1@127.028,105.41 127.028,106.426 v1(127.155,106.553)
  Inner2 w0.5: v1(119.281,115.57) 119.654,115.943 127.29,115.943 v1(128.933,114.3)
  Bottom Layer w0.4: v1(127.155,106.553) 128.933,108.331 v1(128.933,114.3)
  Bottom Layer w0.5: v1(119.281,115.57) 119.281,114.726 U1.4
SIM_RST: R14.1 U2.17 | length 4
  Top Layer w0.5: U2.17 122.969,114.808 126.004,114.808 126.139,114.672 R14.1
SIM_VDD: C33.2 D5.3 R30.2 U1.1 U2.14 | length 31.6
  Top Layer w0.34: U2.14 125.157,110.905 v1(125.25,110.998)
  Top Layer w0.5: C33.2 128.417,105.717 R30.2 129.568,107.95 130.076,108.458 130.076,111.379 v1(129.695,111.76)
  Inner2 w0.3: v1(113.566,111.125) 113.82,111.379 v1(116.995,111.379)
  Inner2 w0.34: v1(125.25,110.998) 125.631,111.379
  Inner2 w0.5: v1(116.995,111.379) 125.631,111.379 126.012,111.76 v1(129.695,111.76)
  Bottom Layer w0.3: v1(113.566,111.125) 113.566,110.571 D5.3
  Bottom Layer w0.5: v1(116.995,111.379) 116.995,112.522 117.503,113.03 119.219,113.03 U1.1
SLEEP_IND: Q8.1 U2.3 | length 7.3
  Top Layer w0.5: v1(121.313,93.472) 122.933,93.472 U2.3
  Bottom Layer w0.5: Q8.1 116.883,93.711 117.503,93.091 120.932,93.091 v1(121.313,93.472)
STATUS: Q6.1 U2.61 | length 4.9
  Top Layer w0.5: U2.61 102.517,89.306 v1(102.517,90.932)
  Bottom Layer w0.5: Q6.1 101.897,93.663 101.882,93.648 101.882,92.716 102.517,92.081 v1(102.517,90.932)
USB_DM: L2.4 U2.70 | length 4.9
  Top Layer w0.5: v1(114.166,87.63) U2.70
  Bottom Layer w0.4: v1(114.166,87.63) 114.201,87.665 114.201,89.027 114.475,89.3 L2.4
USB_DP: L2.3 U2.69 | length 9.3
  Top Layer w0.5: U2.69 112.866,86.679 113.312,86.233 v1(113.312,85.598)
  Bottom Layer w0.3: v1(113.312,85.598) 115.471,85.598 116.233,86.36 116.233,88.234 L2.3
VBAT: C1.2 C2.2 C3.2 C37.2 C38.2 C39.2 C40.2 C43.2 C44.2 C47.2 C68.1 C69.1 C71.2 C72.1 D7.1 LED1.1 LED3.2 R23.1 R28.2 R29.2 R38.2 R40.2 R62.2 R77.1 R80.2 U2.57 U2.58 U2.59 U2.60 U2.71 U11.4 U21.1 | length 224.8
  Top Layer w0.34: R77.1 81.554,104.784 v1(81.689,104.648) ; C71.2@83.467,89.219 83.467,90.043 83.721,90.297 86.896,90.297 87.912,89.281 v1(88.547,89.281) 88.547,86.308 R80.2
  Top Layer w0.5: LED1.1 127.155,103.085 v1(127.155,104.013) ; R28.2 127.663,122.564 v1(127.663,123.317)
  Top Layer w0.6: R29.2 127.282,122.183 R28.2
  Top Layer w0.7: U2.57@97.31,89.255 U2.57 97.266,88.519 97.266,87.928 98.742,86.452 C68.1 99.163,83.064 D7.1 ; U2.59 99.866,88.519 99.866,87.487 102.39,84.963 LED3.2 105.655,82.714 106.581,81.788 113.566,81.788 114.963,83.185 v1(114.963,86.868) 115.466,87.371 U2.71
  Top Layer w0.75: v1(94.897,93.726) 94.897,93.218 97.31,90.805 97.31,90.043 U2.57@97.31,89.255
  Top Layer w0.85: U2.57@97.266,88.519 U2.59@99.866,88.519 ; U2.57@97.287,90.043 97.31,90.043 U2.60@101.143,90.043 ; U2.57@97.31,89.255 U2.58 U2.59 U2.60 ; U2.59@99.993,88.519 U2.60@101.143,88.519
  Inner2 w0.7: v1(114.963,86.868) 115.471,87.376 115.471,90.043 120.551,95.123 U11.4
  Inner2 w1: v1(88.547,89.281) 91.468,89.281 94.897,92.71 v1(94.897,93.726)
  Inner2 w1.5: v1(94.897,93.726) 94.897,97.917 99.469,102.489 99.469,105.156 98.834,105.791 v1(98.072,105.791) ; v1(127.155,104.013) 130.203,104.013 132.87,106.68 132.87,120.547 131.37,122.047 128.933,122.047 v1(127.663,123.317)
  Bottom Layer w0.34: v1(81.689,104.648) 82.197,105.156 83.848,105.156 88.24,109.547 88.24,117.221 ; 87.531,90.297 v1(88.547,89.281) ; C38.2 99.581,86.055 C43.2
  Bottom Layer w0.4: C47.2@82.197,118.556 82.251,118.609 R23.1
  Bottom Layer w0.5: v1(127.155,104.013) 127.155,99.695 128.298,98.552 R62.2 129.069,96.148 U11.4
  Bottom Layer w0.6: v1(92.738,82.677) 92.803,82.742 C44.2 C38.2@92.803,85.973 ; C38.2 C38.2@92.803,85.973 ; v1(94.897,93.726) 94.897,93.289 94.079,93.289 92.93,92.14 C37.2 92.87,89.983 C40.2 92.803,87.893 C38.2@92.803,85.973 ; C43.2 101.309,84.326 C39.2
  Bottom Layer w0.75: R23.1 85.254,118.609 86.325,117.538 86.515,117.348 86.515,117.221 ; 97.269,112.93 R38.2 cw(c97.962,109.865) 99.977,108.458 cw(c97.02,110.523) R40.2 97.02,105.528 97.282,105.791 v1(98.072,105.791)
  Bottom Layer w1: 86.325,117.538 86.515,117.221 88.24,117.221 92.977,117.221 97.269,112.93
VCC(2.5V-5V): C4.1 C5.1 CN6.1 U17.1 U19.2 U20.2 | length 64.4
  Inner2 w1.75: CN6.1 80.038,86.487 81.943,84.582 107.724,84.582 110.645,81.661 118.392,81.661 119.281,80.772 U17.1
  Bottom Layer w0.4: CN6.1@79.784,87.649 80.654,87.649 80.827,87.476 80.827,88.111 80.943,88.227 81.828,88.227 ; C5.1 82.513,82.961 U20.2@82.256,83.218 ; 81.828,88.227 81.562,87.961 81.562,82.524 U20.2@82.256,83.218 ; 81.828,88.227 81.828,84.088 U20.2 U20.2@82.256,83.218
VCC(3.3V): R45.2 R46.2 R48.2 U10.1 | length 21.2
  Top Layer w0.5: R45.2 91.985,122.936 89.817,122.936 89.436,123.317 U10.1 89.436,126.622 89.669,126.855 98.982,126.855 99.469,126.368 99.469,125.34 R48.2 99.215,125.213 97.556,123.554 R46.2
VDD_EXT: C29.2 C45.1 C46.1 LED2.2 R31.1 R43.2 R44.2 R63.1 U2.7 U8.2 U8.19 U9.2 U18.2 | length 97
  Top Layer w0.5: v1(121.44,98.552) 121.593,98.705 U2.7 123.673,98.705 124.955,99.986 LED2.2 129.487,99.986 R63.1 132.588,100.067 U18.2
  Top Layer w1: v1(94.643,102.235) 95.659,101.219 v1(100.739,101.219)
  Inner2 w0.5: v1(86.896,124.079) 87.023,123.952 v1(87.023,120.523) 87.277,120.777 88.928,120.777 93.881,115.824 93.881,102.997 v1(94.643,102.235)
  Bottom Layer w0.254: R43.2@85.999,123.181 87.658,123.181 R44.2 ; v1(87.023,120.523) 87.4,120.146 U9.2
  Bottom Layer w0.3: 103.406,93.788 103.532,93.662 ; U8.19 U8.2 105.068,92.975 105.754,93.661 106.021,93.661
  Bottom Layer w0.5: R43.2 85.999,123.181 85.999,123.689 86.388,124.079 v1(86.896,124.079) ; 103.532,93.662 104.676,93.662 106.019,93.662 ; 106.021,93.661 C45.1 C46.1
  Bottom Layer w0.75: v1(100.739,101.219) 103.098,98.861 103.098,98.425 ; 103.406,93.788 103.098,94.097 103.098,98.425 ; R31.1 113.185,96.266 112.423,97.028 111.153,97.028 ; v1(121.44,98.552) 112.169,98.552 111.153,97.536 111.153,97.028 ; 103.098,98.425 109.756,98.425 111.153,97.028
WAKEUP_IN: H1.1 Q10.3 R63.2 U2.1 | length 32.4
  Top Layer w0.5: U2.1 122.993,90.932 124.869,90.932 126.012,89.789 v1(126.012,87.63) ; v1(128.044,84.074) 130.457,84.074 131.6,85.217 131.6,90.051 132.1,90.551 132.743,90.551 ; R63.2 129.568,95.123 130.33,94.361 Q10.3 131.854,93.964 131.854,91.44 132.743,90.551 ; H1.1 132.743,90.551
  Bottom Layer w0.5: v1(126.012,87.63) 126.012,86.106 v1(128.044,84.074)
WIFI/BT_ANT: C23.1 U2.35 U5.1 | length 18.5
  Top Layer w0.7: v1(95.966,115.951) U2.35
  Inner1 w0.75: v1@95.93,115.951 ccw(c95.93,128.947) v1@106.037,120.777
  Bottom Layer w0.7: v1(106.073,120.777) 106.073,122.301 106.522,122.75 U5.1
  Bottom Layer w0.75: v1(106.073,120.777) 106.327,120.523 108.022,120.523 C23.1
pads on no net: D5.1 U1.5 U2.4 U2.11 U2.12 U2.13 U2.18 U2.23 U2.24 U2.25 U2.26 U2.27 U2.28 U2.29 U2.30 U2.31 U2.32 U2.33 U2.34 U2.37 U2.38 U2.39 U2.40 U2.43 U2.55 U2.73 U2.74 U2.75 U2.77 U2.78 U2.79 U2.80 U2.81 U2.82 U2.83 U2.84 U2.113 U2.114 U2.115 U2.116 U2.117 U2.118 U2.119 U2.120 U2.121 U2.122 U2.123 U2.124 U2.125 U2.126 U2.127 U2.128 U2.129 U2.130 U2.131 U2.132 U2.133 U2.134 U2.135 U2.136 U2.137 U2.138 U2.139 U2.140 U2.141 U2.142 U2.143 U2.144 U19.3 U19.4 U19.5 U19.6 U19.7

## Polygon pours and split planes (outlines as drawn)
GND on Top Layer (solid, remove dead copper, pour order 0): 76.456,127.273 98.834,127.273 98.834,77.851 76.456,77.851
GND on Bottom Layer (solid, remove dead copper, pour order 4): 94.079,126.937 135.578,126.937 135.578,78.042 94.079,78.042
GND on Top Layer (solid, remove dead copper, pour order 2): 94.166,126.873 135.664,126.873 135.664,77.978 94.166,77.978
VBAT on Inner2 (solid, remove dead copper): 76.456,127.039 135.753,127.039 135.791,127 135.791,77.597 135.918,77.47 76.736,77.47 76.456,77.75

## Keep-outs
Inner2:
  region: 76.456,93.047 93.627,93.047 93.627,115.16 89.942,118.846 76.456,118.846
Board Outline Layer:
  circle w0.025: c78.768,79.883 r1.5
  region: 80.268,79.883 cw(c78.768,79.883) 77.268,79.883 cw(c78.768,79.883)
  circle w0.025: c133.65,79.903 r1.5
  region: 135.15,79.903 cw(c133.65,79.903) 132.15,79.903 cw(c133.65,79.903)
  circle w0.025: c133.612,124.859 r1.5
  region: 135.112,124.859 cw(c133.612,124.859) 132.112,124.859 cw(c133.612,124.859)
  circle w0.025: c78.75,124.821 r1.5
  region: 80.25,124.821 cw(c78.75,124.821) 77.25,124.821 cw(c78.75,124.821)
  lines w0.254: 76.228,77.381 136.228,77.381 136.228,127.381 76.228,127.381 76.228,77.381

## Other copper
Bottom Layer:
  region net GND: 76.666,93.691 82.223,93.691 82.223,89.4 76.666,89.4
  region net GND: 76.666,94.084 89.353,94.084 89.353,92.19 76.666,92.19
  region net VBAT: 82.959,90.678 89.406,90.678 89.406,89.267 82.959,89.267
  region net $1N55959: 86.183,88.101 88.801,88.101 88.801,80.137 86.183,80.137
  region net VCC(2.5V-5V): 76.456,88.52 81.867,88.52 81.867,81.755 76.456,81.755

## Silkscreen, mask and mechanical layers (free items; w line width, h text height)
Bottom Silkscreen Layer:
  text "QUECTEL_EC200U_MODULE_V1.1" at 114.963,100.33 h1.47
Bottom Solder Mask Layer:
  lines w0.34: 78.895,106.577 78.998,106.68
  lines w1: 79.539,104.276 79.539,106.68
Mechanical Layer:
  circle w0.025: c78.768,79.883 r1.5
  circle w0.025: c133.65,79.903 r1.5
  circle w0.025: c133.612,124.859 r1.5
  circle w0.025: c78.75,124.821 r1.5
